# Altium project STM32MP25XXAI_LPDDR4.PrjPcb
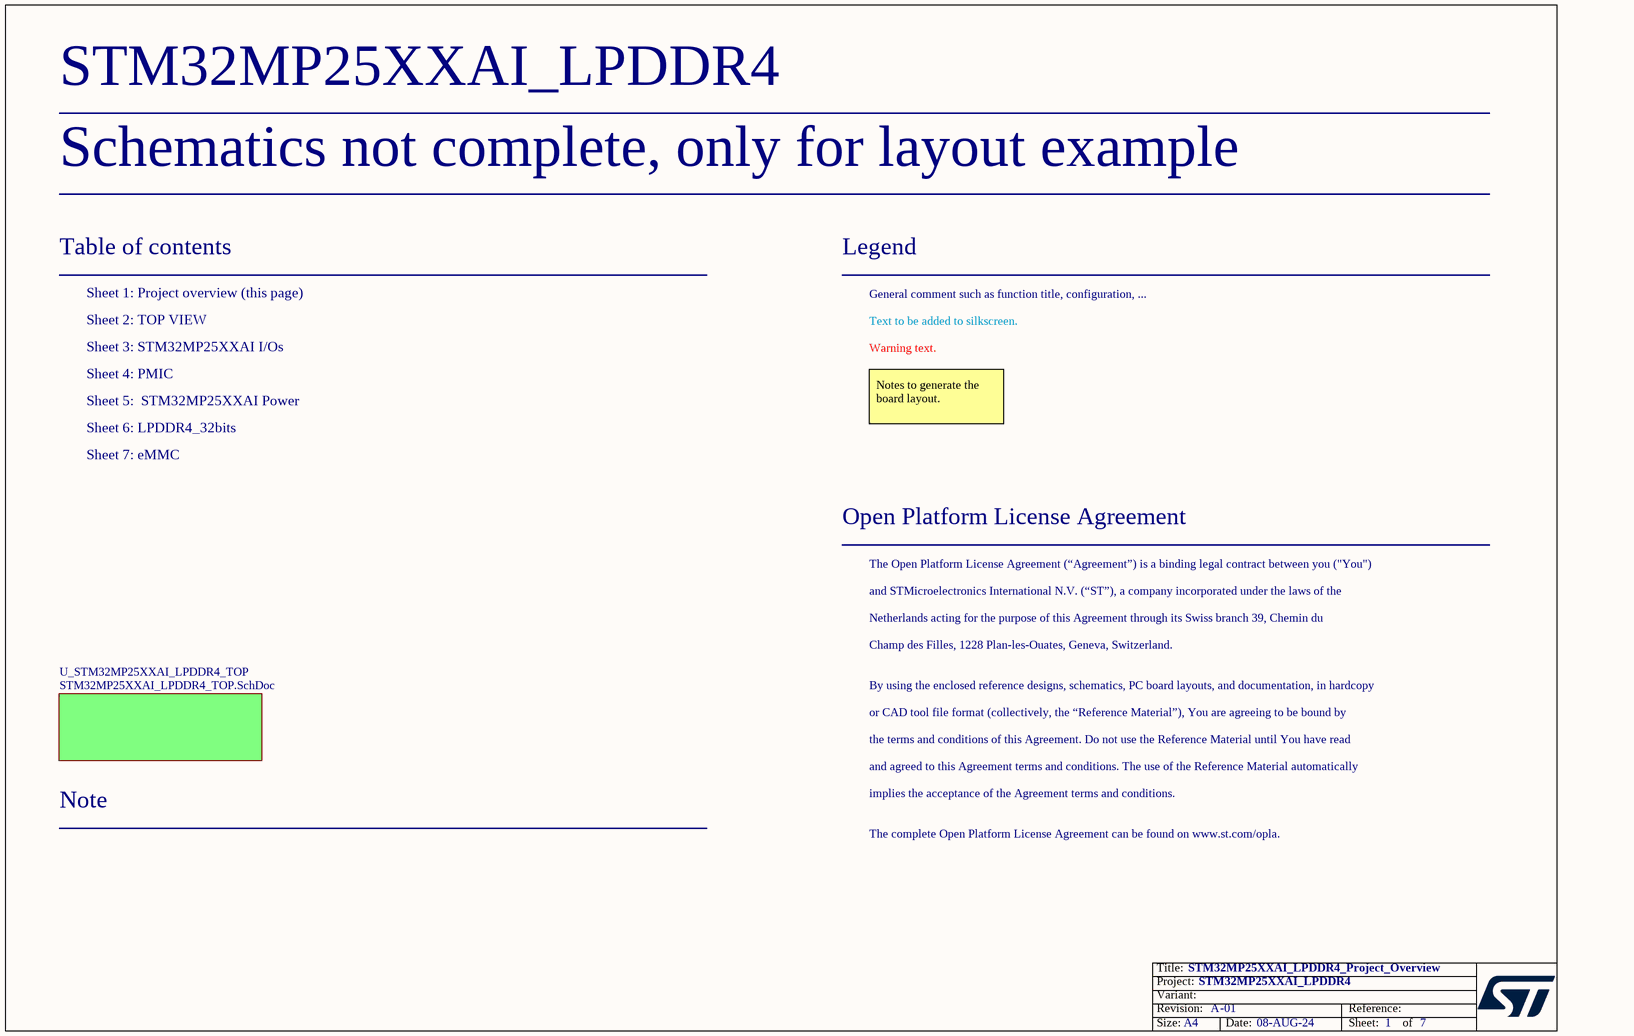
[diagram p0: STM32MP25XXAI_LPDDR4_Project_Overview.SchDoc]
Board_Assembly_Revision: 01; Board_Document_Date: 08-AUG-24; Board_Name: STM32MP25XXAI_LPDDR4; Board_PCB_Revision: A
7 sheets, 188 parts. Net scope: flat (ports and power ports of the same name join across sheets).
Board file: STM32MP25XXAI_LPDDR4.PcbDoc
Sheets:
  STM32MP25XXAI_LPDDR4_Project_Overview.SchDoc
    U_STM32MP25XXAI_LPDDR4_TOP = STM32MP25XXAI_LPDDR4_TOP.SchDoc
      U_STM32MP25XXAI I_Os = STM32MP25XXAI I_Os.SchDoc
      U_PMIC = PMIC.SchDoc
      U_STM32MP25XXAI Power = STM32MP25XXAI Power.SchDoc
      U_eMMC = eMMC.SchDoc
      U_2_LPDDR4_32bits = LPDDR4_32bits.SchDoc

## Sheet STM32MP25XXAI_LPDDR4_Project_Overview.SchDoc: STM32MP25XXAI_LPDDR4_Project_Overview
size A4; Date: Not used; ApprovedBy: Not used; CheckedBy: Not used; Author: Not used; CompanyName: STMicroelectronics; DrawnBy: Not used; Engineer: Not used; Organization: Not used; Address1: Not used; Address2: Not used; Address3: Not used; Address4: Not used; DocumentNumber: 1; Revision: Not used; SheetNumber: 1; SheetTotal: 7

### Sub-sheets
U_STM32MP25XXAI_LPDDR4_TOP = STM32MP25XXAI_LPDDR4_TOP.SchDoc: no entries

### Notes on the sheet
- Schematics not complete, only for layout example
- Table of contents
- Sheet 1: Project overview (this page)
- Legend
- General comment such as function title, configuration, ...
- Sheet 2: TOP VIEW
- Sheet 3: STM32MP25XXAI I/Os
- Sheet 4: PMIC
- Text to be added to silkscreen.
- Warning text.
- Sheet 5:  STM32MP25XXAI Power
- Sheet 6: LPDDR4_32bits
- Notes to generate the board layout.
- Sheet 7: eMMC
- Open Platform License Agreement
- The Open Platform License Agreement (“Agreement”) is a binding legal contract between you ("You")
- and STMicroelectronics International N.V. (“ST”), a company incorporated under the laws of the
- Netherlands acting for the purpose of this Agreement through its Swiss branch 39, Chemin du
- Champ des Filles, 1228 Plan-les-Ouates, Geneva, Switzerland.
- By using the enclosed reference designs, schematics, PC board layouts, and documentation, in hardcopy
- or CAD tool file format (collectively, the “Reference Material”), You are agreeing to be bound by
- the terms and conditions of this Agreement. Do not use the Reference Material until You have read
- and agreed to this Agreement terms and conditions. The use of the Reference Material automatically
- Note
- implies the acceptance of the Agreement terms and conditions.
- The complete Open Platform License Agreement can be found on www.st.com/opla.

## Sheet STM32MP25XXAI_LPDDR4_TOP.SchDoc: TOP
size A4; Date: Not used; ApprovedBy: Not used; CheckedBy: Not used; Author: Not used; CompanyName: STMicroelectronics; DrawnBy: Not used; Engineer: Not used; Organization: Not used; Address1: Not used; Address2: Not used; Address3: Not used; Address4: Not used; DocumentNumber: 2; Revision: Not used; SheetNumber: 2; SheetTotal: 7
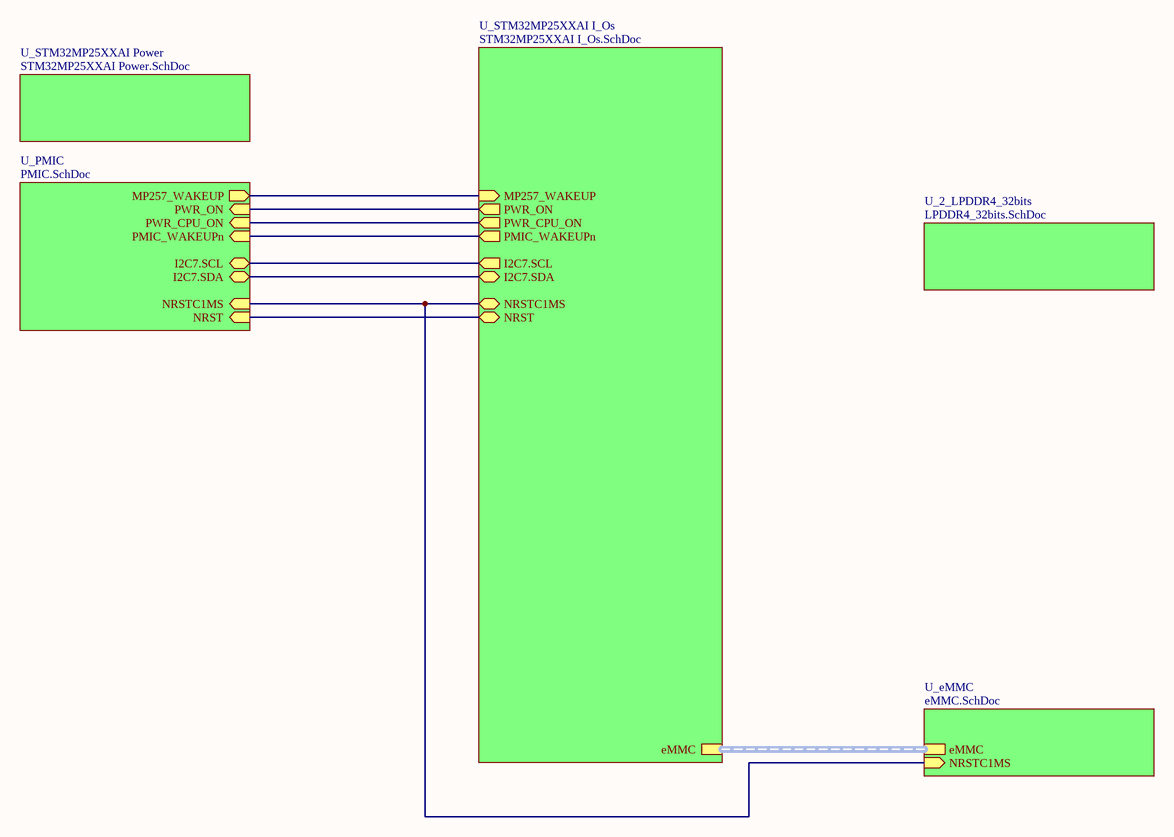
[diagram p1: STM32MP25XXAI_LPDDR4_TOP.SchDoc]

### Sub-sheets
U_2_LPDDR4_32bits = LPDDR4_32bits.SchDoc: no entries
U_eMMC = eMMC.SchDoc: eMMC (harness eMMC), NRSTC1MS (in)
U_PMIC = PMIC.SchDoc: PMIC_WAKEUPn (in), NRST (in), I2C7.SCL (bidir), PWR_ON (in), PWR_CPU_ON (in), NRSTC1MS (in), I2C7.SDA (bidir), MP257_WAKEUP (out)
U_STM32MP25XXAI I_Os = STM32MP25XXAI I_Os.SchDoc: NRST (bidir), PWR_ON (out), NRSTC1MS (bidir), I2C7.SDA (bidir), I2C7.SCL (out), PWR_CPU_ON (out), MP257_WAKEUP (in), PMIC_WAKEUPn (out), eMMC (harness eMMC)
U_STM32MP25XXAI Power = STM32MP25XXAI Power.SchDoc: no entries

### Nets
(unnamed): sheet U_STM32MP25XXAI I_Os/NRST, sheet U_PMIC/NRST
(unnamed): sheet U_STM32MP25XXAI I_Os/PWR_ON, sheet U_PMIC/PWR_ON  [a separate net that carries the same name]
(unnamed): sheet U_STM32MP25XXAI I_Os/NRSTC1MS, sheet U_PMIC/NRSTC1MS, sheet U_eMMC/NRSTC1MS  [a separate net that carries the same name]
(unnamed): sheet U_STM32MP25XXAI I_Os/I2C7.SDA, sheet U_PMIC/I2C7.SDA  [a separate net that carries the same name]
(unnamed): sheet U_STM32MP25XXAI I_Os/I2C7.SCL, sheet U_PMIC/I2C7.SCL  [a separate net that carries the same name]
(unnamed): sheet U_STM32MP25XXAI I_Os/PWR_CPU_ON, sheet U_PMIC/PWR_CPU_ON  [a separate net that carries the same name]
(unnamed): sheet U_STM32MP25XXAI I_Os/MP257_WAKEUP, sheet U_PMIC/MP257_WAKEUP  [a separate net that carries the same name]
(unnamed): sheet U_STM32MP25XXAI I_Os/PMIC_WAKEUPn, sheet U_PMIC/PMIC_WAKEUPn  [a separate net that carries the same name]

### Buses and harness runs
harness sheet U_eMMC/eMMC = sheet U_STM32MP25XXAI I_Os/eMMC

## Sheet STM32MP25XXAI I_Os.SchDoc: STM32MP25XXAI  I/Os
size A3; Date: Not used; ApprovedBy: Not used; CheckedBy: Not used; Author: Not used; CompanyName: STMicroelectronics; DrawnBy: Not used; Engineer: Not used; Organization: Not used; Address1: Not used; Address2: Not used; Address3: Not used; Address4: Not used; DocumentNumber: 3; Revision: Not used; SheetNumber: 3; SheetTotal: 7
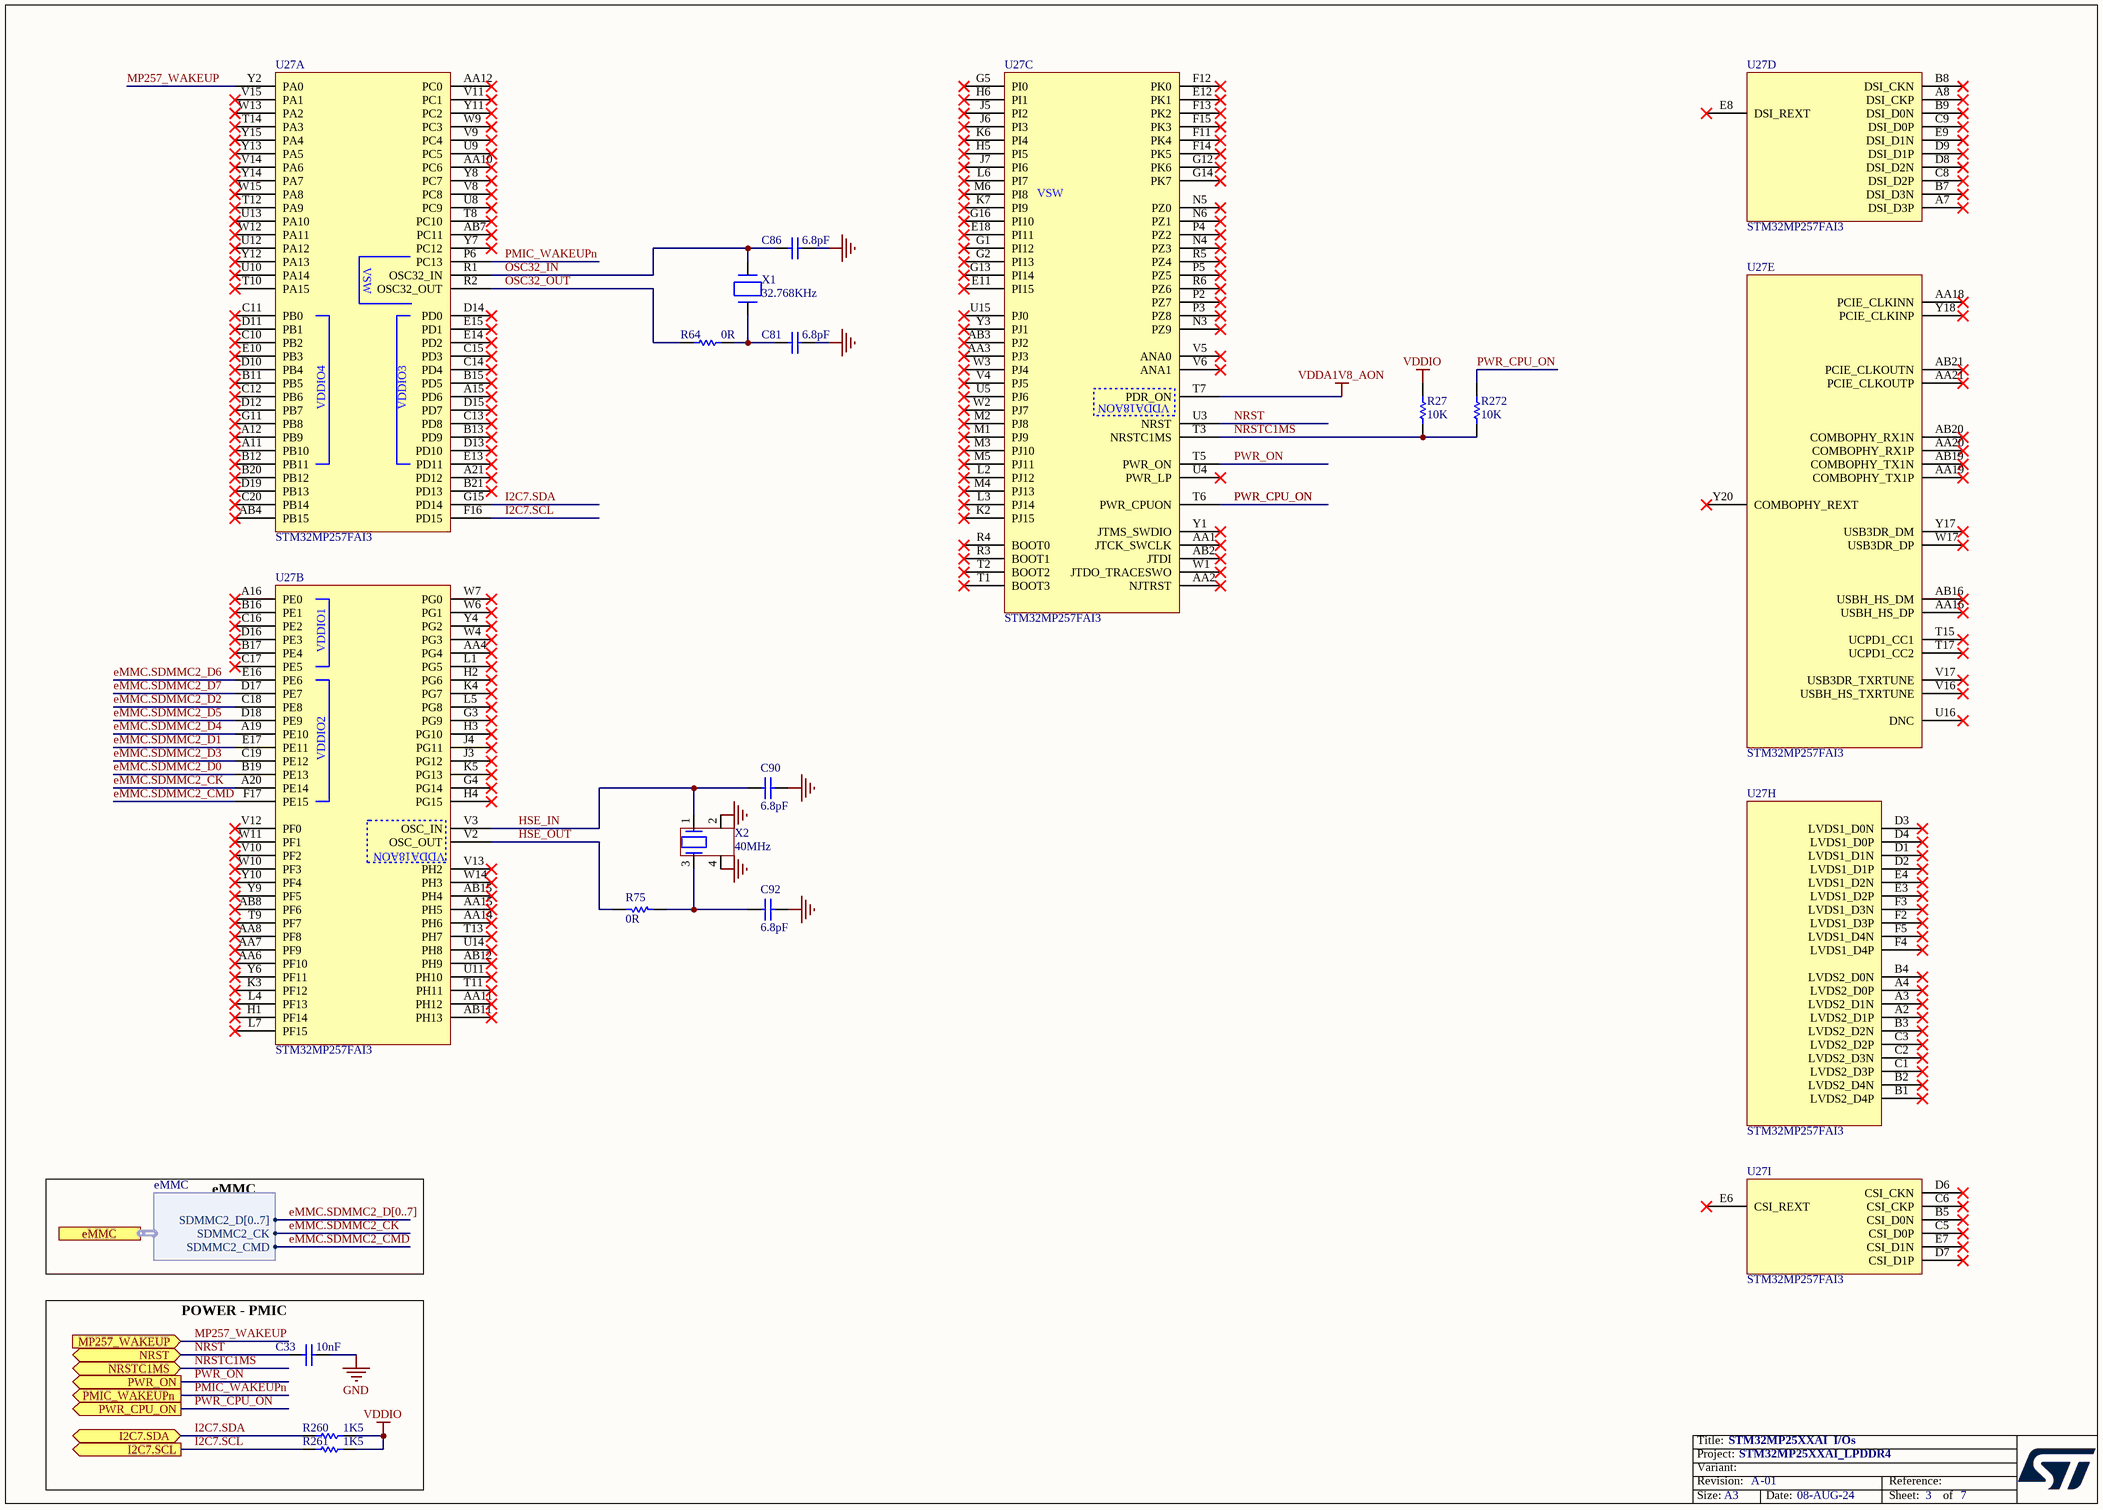
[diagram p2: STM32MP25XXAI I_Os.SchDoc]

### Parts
C33  value 10nF  [C0402]  (hidden comment: Capacitor)
C81  value 6.8pF  [C0402]  (hidden comment: Capacitor)
C86  value 6.8pF  [C0402]  (hidden comment: Capacitor)
C90  value 6.8pF  [C0402]  (hidden comment: Capacitor)
C92  value 6.8pF  [C0402]  (hidden comment: Capacitor)
R27  value 10K  [R0402]  (hidden comment: Resistor)
R64  value 0R  [R0402]
R75  value 0R  [R0402]
R260  value 1K5  [R0402]  (hidden comment: Resistor)
R261  value 1K5  [R0402]  (hidden comment: Resistor)
R272  value 10K  [R0402]  (hidden comment: Resistor)
U27  STM32MP257FAI3  [ICC_LFBGA436_18X18_P080_H1P70_STM32MP257_CODE-B0D1]  (parts A,B,C,D,E,H,I of 9)
X1  value 32.768KHz  [CRY_NX2012SA_2P]  (hidden comment: XTAL_2_PINS)
X2  value 40MHz  [CRY_NX1612SA_4P]  (hidden comment: XTAL_4_PINS)

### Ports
eMMC (harness eMMC), I2C7.SCL (out), I2C7.SDA (bidir), MP257_WAKEUP (in), NRST (bidir), NRSTC1MS (bidir), PMIC_WAKEUPn (out), PWR_CPU_ON (out), PWR_ON (out)

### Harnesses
eMMC: SDMMC2_CK, SDMMC2_CMD, SDMMC2_D[0..7]

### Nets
GND: C33.1 C81.2 C86.2 C90.1 C92.2 X2.2 X2.4
VDDA1V8_AON: U27.T7(PDR_ON)
VDDIO: R27.2 R260.2 R261.2
eMMC.SDMMC2_CK: U27.A20(PE14) ; port eMMC.SDMMC2_CK
eMMC.SDMMC2_CMD: U27.F17(PE15) ; port eMMC.SDMMC2_CMD
eMMC.SDMMC2_D0: U27.B19(PE13)
eMMC.SDMMC2_D1: U27.E17(PE11)
eMMC.SDMMC2_D2: U27.C18(PE8)
eMMC.SDMMC2_D3: U27.C19(PE12)
eMMC.SDMMC2_D4: U27.A19(PE10)
eMMC.SDMMC2_D5: U27.D18(PE9)
eMMC.SDMMC2_D6: U27.E16(PE6)
eMMC.SDMMC2_D7: U27.D17(PE7)
HSE_IN: C90.2 U27.V3(OSC_IN) X2.1
HSE_OUT: R75.2 U27.V2(OSC_OUT)
I2C7.SCL: R261.1 U27.F16(PD15) ; port I2C7.SCL
I2C7.SDA: R260.1 U27.G15(PD14) ; port I2C7.SDA
MP257_WAKEUP: U27.Y2(PA0) ; port MP257_WAKEUP
NRST: C33.2 U27.U3(NRST) ; port NRST
NRSTC1MS: R27.1 R272.1 U27.T3(NRSTC1MS) ; port NRSTC1MS
OSC32_IN: C86.1 U27.R1(OSC32_IN) X1.2(X2)
OSC32_OUT: R64.1 U27.R2(OSC32_OUT)
PMIC_WAKEUPn: U27.P6(PC13) ; port PMIC_WAKEUPn
PWR_CPU_ON: R272.2 U27.T6(PWR_CPUON) ; port PWR_CPU_ON
PWR_ON: U27.T5(PWR_ON) ; port PWR_ON
NetC81_1: C81.1 R64.2 X1.1(X1)
NetC92_1: C92.1 R75.1 X2.3

Not connected (* = marked no-connect by the designer): U27 A2(LVDS2_D1P)* A3(LVDS2_D1N)* A4(LVDS2_D0P)* A7(DSI_D3P)* A8(DSI_CKP)* A11(PB10)* A12(PB9)* A15(PD6)* A16(PE0)* A21(PD12)* AA1(JTCK_SWCLK)* AA2(NJTRST)* AA3(PJ3)* AA4(PG4)* AA6(PF10)* AA7(PF9)* AA8(PF8)* AA10(PC6)* AA11(PH12)* AA12(PC0)* AA14(PH6)* AA15(PH5)* AA16(USBH_HS_DP)* AA18(PCIE_CLKINN)* AA19(COMBOPHY_TX1P)* AA20(COMBOPHY_RX1P)* AA21(PCIE_CLKOUTP)* AB2(JTDI)* AB3(PJ2)* AB4(PB15)* AB7(PC11)* AB8(PF6)* AB11(PH13)* AB12(PH9)* AB15(PH4)* AB16(USBH_HS_DM)* AB19(COMBOPHY_TX1N)* AB20(COMBOPHY_RX1N)* AB21(PCIE_CLKOUTN)* B1(LVDS2_D4P)* B2(LVDS2_D4N)* B3(LVDS2_D2N)* B4(LVDS2_D0N)* B5(CSI_D0N)* B7(DSI_D3N)* B8(DSI_CKN)* B9(DSI_D0N)* B11(PB5)* B12(PB11)* B13(PD9)* B15(PD5)* B16(PE1)* B17(PE4)* B20(PB12)* B21(PD13)* C1(LVDS2_D3P)* C2(LVDS2_D3N)* C3(LVDS2_D2P)* C5(CSI_D0P)* C6(CSI_CKP)* C8(DSI_D2P)* C9(DSI_D0P)* C10(PB2)* C11(PB0)* C12(PB6)* C13(PD8)* C14(PD4)* C15(PD3)* C16(PE2)* C17(PE5)* C20(PB14)* D1(LVDS1_D1N)* D2(LVDS1_D1P)* D3(LVDS1_D0N)* D4(LVDS1_D0P)* D6(CSI_CKN)* D7(CSI_D1P)* D8(DSI_D2N)* D9(DSI_D1P)* D10(PB4)* D11(PB1)* D12(PB7)* D13(PD10)* D14(PD0)* D15(PD7)* D16(PE3)* D19(PB13)* E3(LVDS1_D2P)* E4(LVDS1_D2N)* E6(CSI_REXT)* E7(CSI_D1N)* E8(DSI_REXT)* E9(DSI_D1N)* E10(PB3)* E11(PI15)* E12(PK1)* E13(PD11)* E14(PD2)* E15(PD1)* E18(PI11)* F2(LVDS1_D3P)* F3(LVDS1_D3N)* F4(LVDS1_D4P)* F5(LVDS1_D4N)* F11(PK4)* F12(PK0)* F13(PK2)* F14(PK5)* F15(PK3)* G1(PI12)* G2(PI13)* G3(PG9)* G4(PG14)* G5(PI0)* G11(PB8)* G12(PK6)* G13(PI14)* G14(PK7)* G16(PI10)* H1(PF14)* H2(PG6)* H3(PG10)* H4(PG15)* H5(PI5)* H6(PI1)* J3(PG12)* J4(PG11)* J5(PI2)* J6(PI3)* J7(PI6)* K2(PJ15)* K3(PF12)* K4(PG7)* K5(PG13)* K6(PI4)* K7(PI9)* L1(PG5)* L2(PJ12)* L3(PJ14)* L4(PF13)* L5(PG8)* L6(PI7)* L7(PF15)* M1(PJ9)* M2(PJ8)* M3(PJ10)* M4(PJ13)* M5(PJ11)* M6(PI8)* N3(PZ9)* N4(PZ3)* N5(PZ0)* N6(PZ1)* P2(PZ7)* P3(PZ8)* P4(PZ2)* P5(PZ5)* R3(BOOT1)* R4(BOOT0)* R5(PZ4)* R6(PZ6)* T1(BOOT3)* T2(BOOT2)* T8(PC10)* T9(PF7)* T10(PA15)* T11(PH11)* T12(PA9)* T13(PH7)* T14(PA3)* T15(UCPD1_CC1)* T17(UCPD1_CC2)* U4(PWR_LP)* U5(PJ6)* U8(PC9)* U9(PC5)* U10(PA14)* U11(PH10)* U12(PA12)* U13(PA10)* U14(PH8)* U15(PJ0)* U16(DNC)* V4(PJ5)* V5(ANA0)* V6(ANA1)* V8(PC8)* V9(PC4)* V10(PF2)* V11(PC1)* V12(PF0)* V13(PH2)* V14(PA6)* V15(PA1)* V16(USBH_HS_TXRTUNE)* V17(USB3DR_TXRTUNE)* W1(JTDO_TRACESWO)* W2(PJ7)* W3(PJ4)* W4(PG3)* W6(PG1)* W7(PG0)* W9(PC3)* W10(PF3)* W11(PF1)* W12(PA11)* W13(PA2)* W14(PH3)* W15(PA8)* W17(USB3DR_DP)* Y1(JTMS_SWDIO)* Y3(PJ1)* Y4(PG2)* Y6(PF11)* Y7(PC12)* Y8(PC7)* Y9(PF5)* Y10(PF4)* Y11(PC2)* Y12(PA13)* Y13(PA5)* Y14(PA7)* Y15(PA4)* Y17(USB3DR_DM)* Y18(PCIE_CLKINP)* Y20(COMBOPHY_REXT)*

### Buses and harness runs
bus eMMC.SDMMC2_D[0..7]

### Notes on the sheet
- eMMC
- POWER - PMIC

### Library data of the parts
C33 = MCD-00011: Capacitor, MLCC, 10nF, 16V, X7R, 10%, 0402, T=0.5mm; Manufacturer_Part_Number: CC0402KRX7R7BB103; Manufacturer: YAGEO; Provided_By: SUBCO; Initial_Board_Reference: MB1274
C81 C86 = MCD-00674: Capacitor, MLCC, 6.8pF, 50V, NPO, +-0.25pF, 0402, T=0.5mm; Manufacturer_Part_Number: CC0402CRNPO9BN6R8; Manufacturer: YAGEO; Part_Preference: Recommended; Provided_By: SUBCO; Initial_Board_Reference: MB1319; Path: ws/MCD_ApplicationBoards/Lists/MCDPARTSdatabase; Item Type: Item; Component_Country_Of_Origin: China; ID: 3068; ShowFields: YES
C90 C92 = MCD-00674: Capacitor, MLCC, 6.8pF, 50V, NPO, +-0.25pF, 0402, T=0.5mm; Manufacturer_Part_Number: CC0402CRNPO9BN6R8; Manufacturer: YAGEO; Part_Preference: Recommended; Provided_By: SUBCO; Initial_Board_Reference: MB1319; Component_Country_Of_Origin: China; ID: 3068; ShowFields: YES
R27 R272 = MCD-00053: Resistor,10K,0402,1%,1/16W; BMS_Part_Number: 9131590; Part_Preference: Recommended; Manufacturer: YAGEO; Manufacturer_Part_Number: RC0402FR-0710KL; Component_Country_Of_Origin: China; ID: 2539; ShowFields: YES
R64 R75 = MCD-00052: Resistor,0R,0402,5%,1/16W; Manufacturer_Part_Number: RC0402JR-070RL; Manufacturer: YAGEO; Part_Preference: Recommended; Provided_By: SUBCO; Initial_Board_Reference: mb1274; Order_Code_RS: 618-5804; Component_Country_Of_Origin: China; ID: 2540; ShowFields: YES
R260 R261 = MCD-00068: Resistor,1K5,0402,1%,1/16W; Part_Preference: Recommended; Manufacturer: YAGEO; Manufacturer_Part_Number: RC0402FR-071K5L; Component_Country_Of_Origin: China; ID: 2524; ShowFields: YES
U27 = MCD-02000: MPU, ARM Cortex-A35 + M33 32-bit MPU, 808KB RAM, With Crypto; Part_Type: IC; Part_Preference: Recommended; Manufacturer: STMICROELECTRONICS; Manufacturer_HQ_COO: EU; Component_Country_Of_Origin: Unknown; ShowFields: YES; ID: 4100
X1 = MCD-01479: Crystal, 32.768kHz, 6pF, +/-20ppm, 80K, 2.05x1.2mm; BMS_Part_Number: 9157049; Part_Type: Crystal_Osc; Part_Preference: Recommended; Manufacturer: NDK; Manufacturer_Part_Number: NX2012SA-32.768KHZ-EXS00A-MU00527; Component_Country_Of_Origin: Unknown; ShowFields: YES; ID: 3579
X2 = MCD-02344: Crystal, 40MHz, 6pF, +/-20ppm, 80R, 1.6x1.2mm; Part_Type: Crystal_Osc; Part_Preference: Recommended; Manufacturer: NDK; Manufacturer_Part_Number: NX1612SA-40MHZ-EXS00A-CS13836; Component_Country_Of_Origin: Unknown; ShowFields: YES; ID: 4450

## Sheet PMIC.SchDoc: PMIC
size A3; Date: Not used; ApprovedBy: Not used; CheckedBy: Not used; Author: Not used; CompanyName: STMicroelectronics; DrawnBy: Not used; Engineer: Not used; Organization: Not used; Address1: Not used; Address2: Not used; Address3: Not used; Address4: Not used; DocumentNumber: 4; Revision: Not used; SheetNumber: 4; SheetTotal: 7
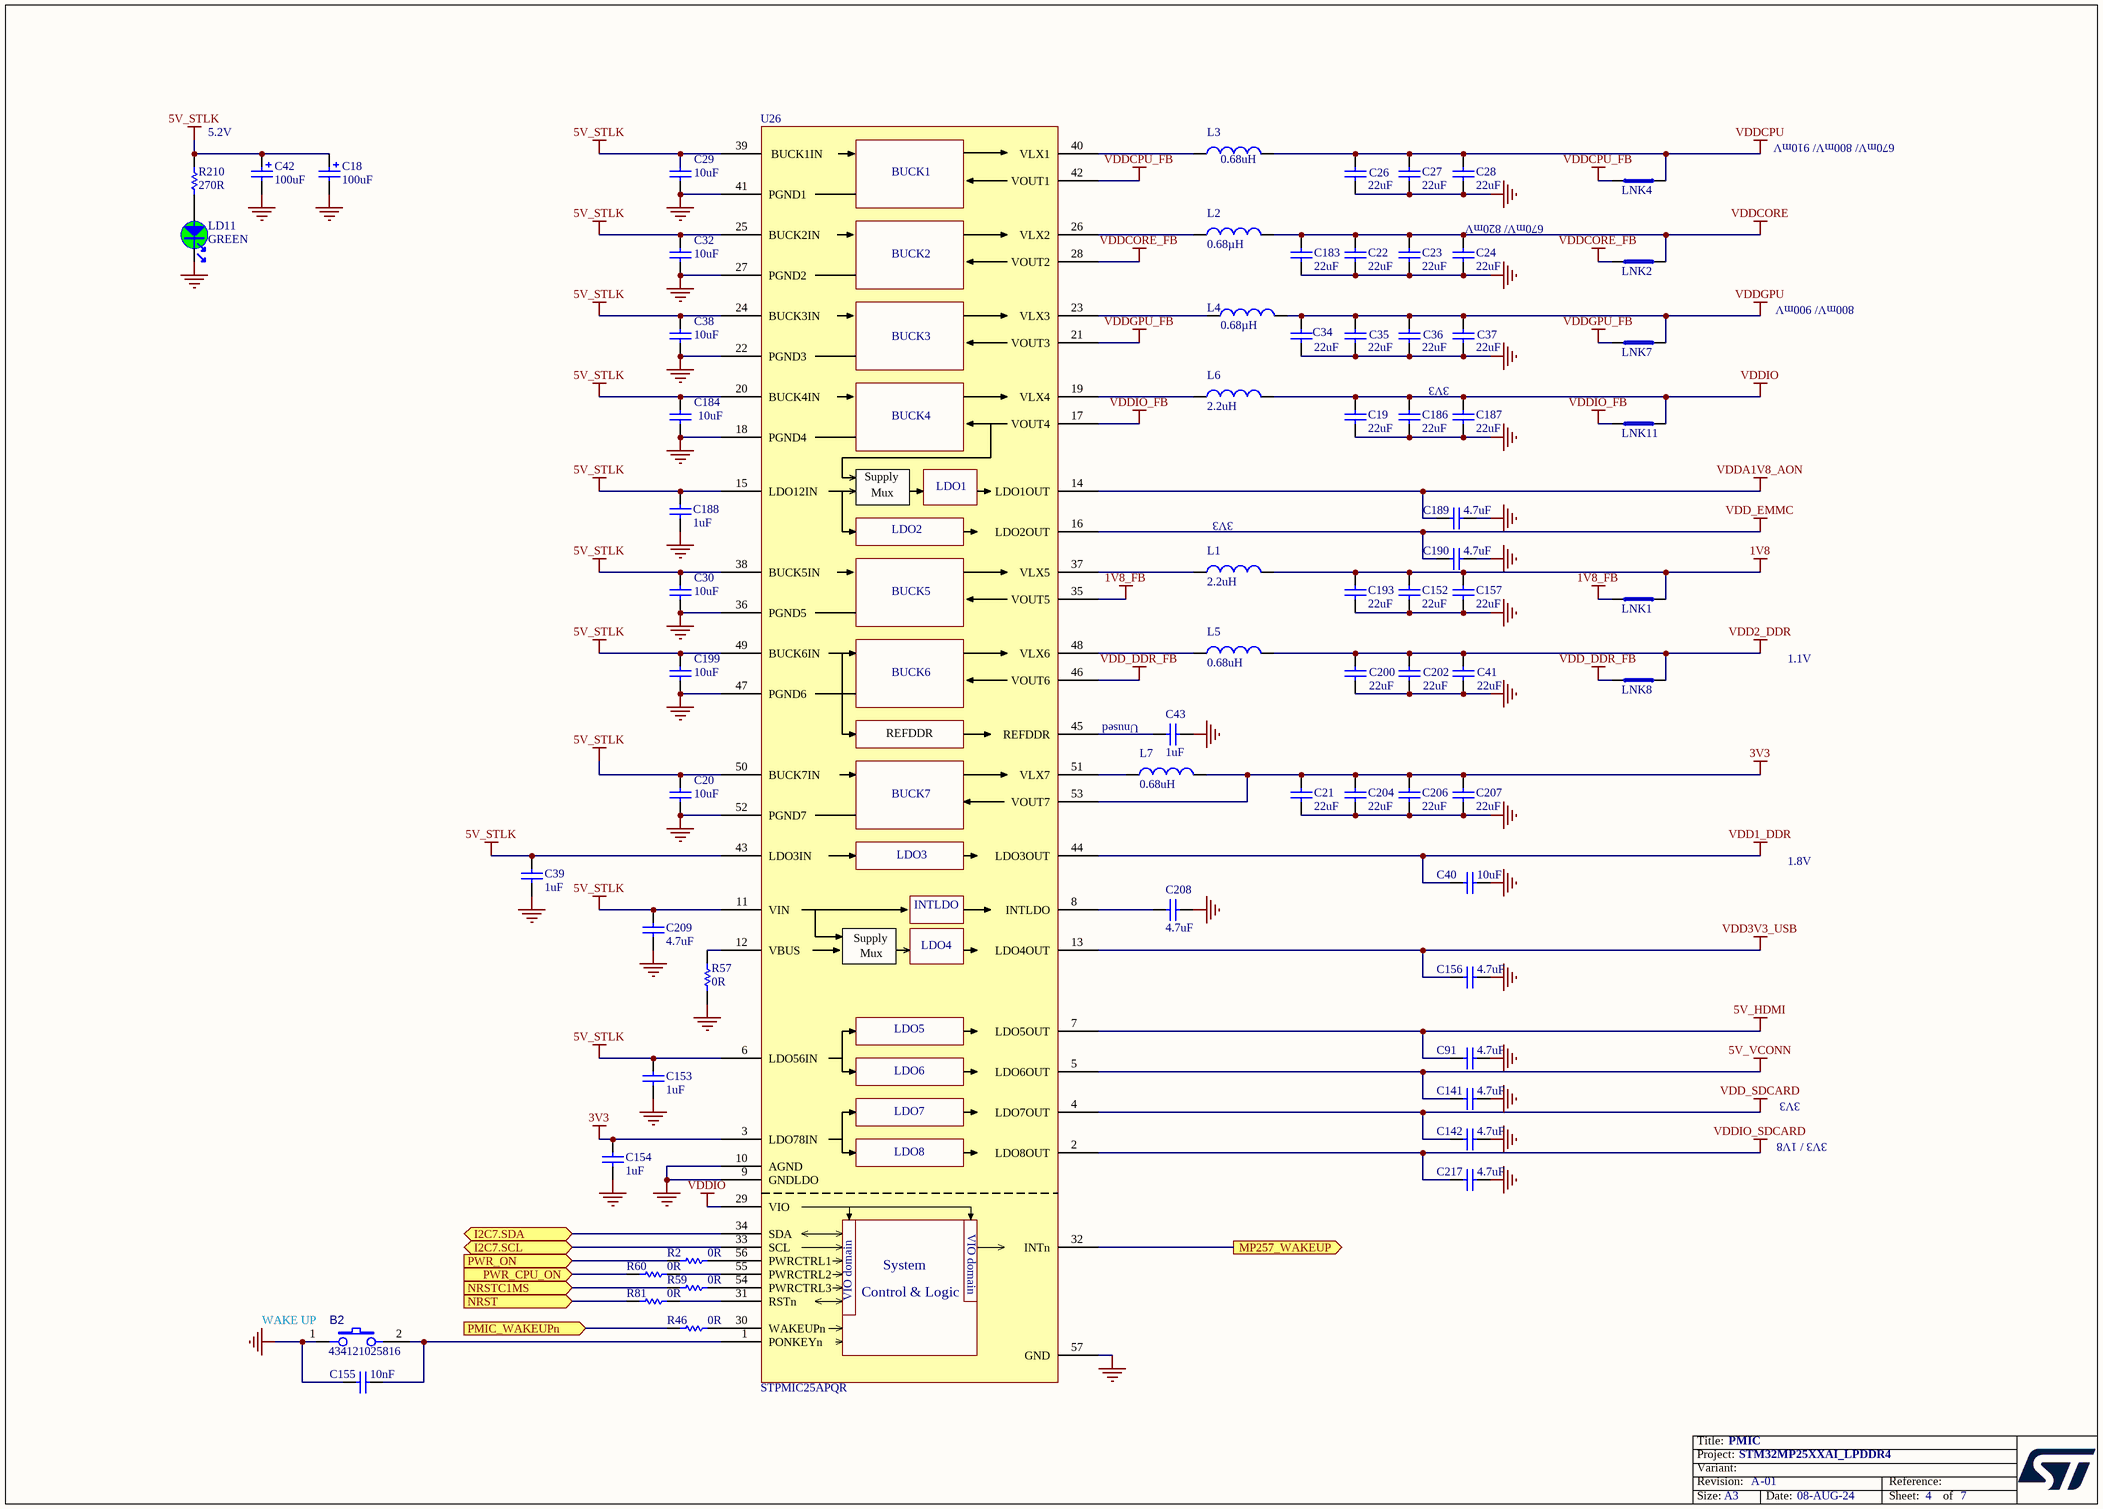
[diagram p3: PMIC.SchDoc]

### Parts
B2  value 434121025816  [SWI_WE_434121025816]  (hidden comment: SW_PUSH_SMD_2P)
C18  value 100uF  [CPOL_TCJ-B_1210_H210]  (hidden comment: Cap_POL_TANA)
C19  value 22uF  [C0805]  (hidden comment: Capacitor)
C20  value 10uF  [C0603]  (hidden comment: Capacitor)
C21  value 22uF  [C0805]  (hidden comment: Capacitor)
C22  value 22uF  [C0603]  (hidden comment: Capacitor)
C23  value 22uF  [C0603]  (hidden comment: Capacitor)
C24  value 22uF  [C0603]  (hidden comment: Capacitor)
C26  value 22uF  [C0603]  (hidden comment: Capacitor)
C27  value 22uF  [C0603]  (hidden comment: Capacitor)
C28  value 22uF  [C0603]  (hidden comment: Capacitor)
C29  value 10uF  [C0603]  (hidden comment: Capacitor)
C30  value 10uF  [C0603]  (hidden comment: Capacitor)
C32  value 10uF  [C0603]  (hidden comment: Capacitor)
C34  value 22uF  [C0603]  (hidden comment: Capacitor)
C35  value 22uF  [C0603]  (hidden comment: Capacitor)
C36  value 22uF  [C0603]  (hidden comment: Capacitor)
C37  value 22uF  [C0603]  (hidden comment: Capacitor)
C38  value 10uF  [C0603]  (hidden comment: Capacitor)
C39  value 1uF  [C0402]  (hidden comment: Capacitor)
C40  value 10uF  [C0402]  (hidden comment: Capacitor)
C41  value 22uF  [C0603]  (hidden comment: Capacitor)
C42  value 100uF  [CPOL_TCJ-B_1210_H210]  (hidden comment: Cap_POL_TANA)
C43  value 1uF  [C0402]  (hidden comment: Capacitor)
C91  value 4.7uF  [C0402]  (hidden comment: Capacitor)
C141  value 4.7uF  [C0402]  (hidden comment: Capacitor)
C142  value 4.7uF  [C0402]  (hidden comment: Capacitor)
C152  value 22uF  [C0805]  (hidden comment: Capacitor)
C153  value 1uF  [C0402]  (hidden comment: Capacitor)
C154  value 1uF  [C0402]  (hidden comment: Capacitor)
C155  value 10nF  [C0402]  (hidden comment: Capacitor)
C156  value 4.7uF  [C0402]  (hidden comment: Capacitor)
C157  value 22uF  [C0805]  (hidden comment: Capacitor)
C183  value 22uF  [C0603]  (hidden comment: Capacitor)
C184  value 10uF  [C0603]  (hidden comment: Capacitor)
C186  value 22uF  [C0805]  (hidden comment: Capacitor)
C187  value 22uF  [C0805]  (hidden comment: Capacitor)
C188  value 1uF  [C0402]  (hidden comment: Capacitor)
C189  value 4.7uF  [C0402]  (hidden comment: Capacitor)
C190  value 4.7uF  [C0402]  (hidden comment: Capacitor)
C193  value 22uF  [C0805]  (hidden comment: Capacitor)
C199  value 10uF  [C0603]  (hidden comment: Capacitor)
C200  value 22uF  [C0603]  (hidden comment: Capacitor)
C202  value 22uF  [C0603]  (hidden comment: Capacitor)
C204  value 22uF  [C0805]  (hidden comment: Capacitor)
C206  value 22uF  [C0805]  (hidden comment: Capacitor)
C207  value 22uF  [C0805]  (hidden comment: Capacitor)
C208  value 4.7uF  [C0402]  (hidden comment: Capacitor)
C209  value 4.7uF  [C0402]  (hidden comment: Capacitor)
C217  value 4.7uF  [C0402]  (hidden comment: Capacitor)
L1  value 2.2uH  [IND_2016_MURATA_LQM2MPN2R2NG0]  (hidden comment: Inductor)
L2  value 0.68µH  [IND_2520_TOKO_DFE252012P]  (hidden comment: Inductor)
L3  value 0.68uH  [IND_2016_MURATA_LQM2MPN2R2NG0]  (hidden comment: Inductor)
L4  value 0.68µH  [IND_2520_TOKO_DFE252012P]  (hidden comment: Inductor)
L5  value 0.68uH  [IND_2016_MURATA_LQM2MPN2R2NG0]  (hidden comment: Inductor)
L6  value 2.2uH  [IND_2016_MURATA_LQM2MPN2R2NG0]  (hidden comment: Inductor)
L7  value 0.68uH  [IND_2016_MURATA_LQM2MPN2R2NG0]  (hidden comment: Inductor)
LD11  value GREEN  [LED_0603_OSRAM_LG-Q396-PS-35_GREEN_1A2K_H0P4]  (hidden comment: LED_green)
LNK1  link_200  [LINK200]  (value not drawn)  (no BOM)
LNK2  link_200  [LINK200]  (value not drawn)  (no BOM)
LNK4  link_200  [LINK200]  (value not drawn)  (no BOM)
LNK7  link_200  [LINK200]  (value not drawn)  (no BOM)
LNK8  link_200  [LINK200]  (value not drawn)  (no BOM)
LNK11  link_200  [LINK200]  (value not drawn)  (no BOM)
R2  value 0R  [R0402]
R46  value 0R  [R0402]
R57  value 0R  [R0402]
R59  value 0R  [R0402]
R60  value 0R  [R0402]
R81  value 0R  [R0402]
R210  value 270R  [R0402]  (hidden comment: Resistor)
U26  STPMIC25APQR  [ICC_QFN56-EPAD_6P5X6P5_P040]

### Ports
I2C7.SCL (bidir), I2C7.SDA (bidir), MP257_WAKEUP (out), NRST (in), NRSTC1MS (in), PMIC_WAKEUPn (in), PWR_CPU_ON (in), PWR_ON (in)

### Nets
1V8: C152.2 C157.2 C193.2 L1.2 LNK1.2
1V8_FB: LNK1.1 U26.35(VOUT5)
3V3: C21.2 C154.2 C204.2 C206.2 C207.2 L7.2 U26.3(LDO78IN) U26.53(VOUT7)
5V_HDMI: C91.1 U26.7(LDO5OUT)
5V_STLK: C18.1 C20.2 C29.2 C30.2 C32.2 C38.2 C39.2 C42.1 C153.2 C184.2 C188.2 C199.2 C209.2 R210.1 U26.6(LDO56IN) U26.11(VIN) U26.15(LDO12IN) U26.20(BUCK4IN) U26.24(BUCK3IN) U26.25(BUCK2IN) U26.38(BUCK5IN) U26.39(BUCK1IN) U26.43(LDO3IN) U26.49(BUCK6IN) U26.50(BUCK7IN)
5V_VCONN: C141.1 U26.5(LDO6OUT)
GND: B2.1 C18.2 C19.1 C20.1 C21.1 C22.1 C23.1 C24.1 C26.1 C27.1 C28.1 C29.1 C30.1 C32.1 C34.1 C35.1 C36.1 C37.1 C38.1 C39.1 C40.1 C41.1 C42.2 C43.1 C91.2 C141.2 C142.2 C152.1 C153.1 C154.1 C155.1 C156.1 C157.1 C183.1 C184.1 C186.1 C187.1 C188.1 C189.1 C190.2 C193.1 C199.1 C200.1 C202.1 C204.1 C206.1 C207.1 C208.2 C209.1 C217.2 LD11.2 R57.1 U26.9(GNDLDO) U26.10(AGND) U26.18(PGND4) U26.22(PGND3) U26.27(PGND2) U26.36(PGND5) U26.41(PGND1) U26.47(PGND6) U26.52(PGND7) U26.57(GND)
VDD1_DDR: C40.2 U26.44(LDO3OUT)
VDD2_DDR: C41.2 C200.2 C202.2 L5.2 LNK8.2
VDD3V3_USB: C156.2 U26.13(LDO4OUT)
VDD_DDR_FB: LNK8.1 U26.46(VOUT6)
VDD_EMMC: C190.1 U26.16(LDO2OUT)
VDD_SDCARD: C142.1 U26.4(LDO7OUT)
VDDA1V8_AON: C189.2 U26.14(LDO1OUT)
VDDCORE: C22.2 C23.2 C24.2 C183.2 L2.2 LNK2.2
VDDCORE_FB: LNK2.1 U26.28(VOUT2)
VDDCPU: C26.2 C27.2 C28.2 L3.2 LNK4.1
VDDCPU_FB: LNK4.2 U26.42(VOUT1)
VDDGPU: C34.2 C35.2 C36.2 C37.2 L4.2 LNK7.2
VDDGPU_FB: LNK7.1 U26.21(VOUT3)
VDDIO: C19.2 C186.2 C187.2 L6.2 LNK11.2 U26.29(VIO)
VDDIO_FB: LNK11.1 U26.17(VOUT4)
VDDIO_SDCARD: C217.1 U26.2(LDO8OUT)
I2C7.SCL: U26.33(SCL) ; port I2C7.SCL
I2C7.SDA: U26.34(SDA) ; port I2C7.SDA
MP257_WAKEUP: U26.32(INTn) ; port MP257_WAKEUP
NRST: R81.1 ; port NRST
NRSTC1MS: R59.1 ; port NRSTC1MS
PMIC_WAKEUPn: R46.1 ; port PMIC_WAKEUPn
PWR_CPU_ON: R60.1 ; port PWR_CPU_ON
PWR_ON: R2.1 ; port PWR_ON
NetB2_2: B2.2 C155.2 U26.1(PONKEYn)
NetC43_2: C43.2 U26.45(REFDDR)
NetC208_1: C208.1 U26.8(INTLDO)
NetL1_1: L1.1 U26.37(VLX5)
NetL2_1: L2.1 U26.26(VLX2)
NetL3_1: L3.1 U26.40(VLX1)
NetL4_1: L4.1 U26.23(VLX3)
NetL5_1: L5.1 U26.48(VLX6)
NetL6_1: L6.1 U26.19(VLX4)
NetL7_1: L7.1 U26.51(VLX7)
NetLD11_1: LD11.1 R210.2
NetR2_2: R2.2 U26.56(PWRCTRL1)
NetR46_2: R46.2 U26.30(WAKEUPn)
NetR57_2: R57.2 U26.12(VBUS)
NetR59_2: R59.2 U26.54(PWRCTRL3)
NetR60_2: R60.2 U26.55(PWRCTRL2)
NetR81_2: R81.2 U26.31(RSTn)

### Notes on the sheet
- 5.2V
- 670mV/ 800mV/ 910mV
- (near C24) 670mV/ 820mV
- 800mV/ 900mV
- 3V3
- (near L1) 3V3
- Unused
- 1.1V
- 1.8V
- 3V3 / 1V8
- (near B2) WAKE UP

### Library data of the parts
B2 = MCD-03492: Switch tactile, SPST-NO, 50mA, 12V, 6x3.8mm; Part_Type: Misc; Part_Preference: Recommended; Manufacturer: WURTH ELEKTRONIC; Component_Country_Of_Origin: China°; ShowFields: YES; ID: 5608
C18 C42 = MCD-01796: Capacitor, Tantalum, 100uF, 6V3, 40mR, +/-20%,  Type_B (3528 metric), T=1.9mm; Part_Preference: Recommended; Manufacturer: AVX; Manufacturer_Part_Number: TCJB107M006R0040; Component_Country_Of_Origin: Lanskroun; ShowFields: YES; ID: 3896
C19 C21 C152 C157 C186 C187 C193 C204 C206 C207 = MCD-03139: Capacitor, MLCC, 22uF, 10V, X5R, +/-20%, 0805, T=1,25mm; Part_Preference: Recommended; Manufacturer: MURATA; Manufacturer_Part_Number: GRM21BR61A226ME51L; ShowFields: YES; ID: 5255; Component_Country_Of_Origin: China, Japan
C20 C29 C30 C32 C38 C184 C199 = MCD-00099: Capacitor, MLCC, 10uF, 10V, X5R, +/-10%, 0603, T=0,8mm; Manufacturer_Part_Number: GRM188R61A106KE69D; Manufacturer: MURATA; Part_Preference: Recommended; Order_Code_RS: 170-6168; Component_Country_Of_Origin: Japan; ID: 2770; ShowFields: YES
C22-C24 C26 C34-C37 C41 C200 C202 = MCD-00100: Capacitor, MLCC, 22uF, 6V3, X5R, +/-20%, 0603, T=0,8mm; Manufacturer_Part_Number: GRM188R60J226MEA0J; Manufacturer: MURATA; Part_Preference: Recommended; Component_Country_Of_Origin: Japan; ID: 2766; ShowFields: YES
C27 C28 C183 = MCD-00100: Capacitor, MLCC, 22uF, 6V3, X5R, +/-20%, 0603, T=0,8mm; Part_Preference: Recommended; Manufacturer: MURATA; Manufacturer_Part_Number: GRM188R60J226MEA0J; Component_Country_Of_Origin: Japan; ID: 2766; ShowFields: YES
C39 C43 C153 C154 C188 = MCD-00095: Capacitor, MLCC, 1uF, 25V, X5R, +/-10%, 0402, T=0.5mm; Part_Preference: Recommended; Manufacturer: MURATA; Manufacturer_Part_Number: GRM155R61E105KA12; Order_Code_RS: 846-7287; Component_Country_Of_Origin: Japan; ShowFields: YES; ID: 2772
C40 = MCD-03140: Capacitor, MLCC, 10uF, 6.3V, X5R, +/-20%, 0402, T=0.5mm; Part_Preference: Recommended; Manufacturer: MURATA; Manufacturer_Part_Number: GRM155R60J106ME05D; ShowFields: YES; ID: 5256; Component_Country_Of_Origin: China, Japan
C91 C141 C142 C156 C189 C190 C208 C209 C217 = MCD-01356: Capacitor, MLCC, 4.7uF, 6V3, X5R, +/-20%, 0402, T=0.5mm; Manufacturer_Part_Number: GRM155R60J475ME47; Manufacturer: MURATA; Part_Preference: Recommended; Order_Code_RS: 814-5230; Component_Country_Of_Origin: Japan; ShowFields: YES; ID: 3456
C155 = MCD-02198: Capacitor, MLCC, 10nF, 50V, X7R, +/-10%, 0402, T=0.5mm; Manufacturer_Part_Number: CC0402KRX7R9BB103; Manufacturer: YAGEO; Part_Preference: Recommended; Order_Code_RS: 6169644; Component_Country_Of_Origin: China; ShowFields: YES; ID: 4298
L1 L6 = MCD-03143: Inductor, 2.2uH, +/-20%, Itemp= 1700mA, Isat= 2400mA, 0R140, 0806, T=1mm; Part_Preference: Recommended; Manufacturer: MURATA; Manufacturer_Part_Number: DFE201610E-2R2M=P2; ShowFields: YES; ID: 5259; Component_Country_Of_Origin: Vietnam
L2 L4 = MCD-03142: Inductor, 0.68uH, +/-20%, Itemp= 3900mA, Isat= 5400mA, 0R031, 1008, T=1.2mm; Part_Preference: Recommended; Manufacturer: MURATA; Manufacturer_Part_Number: DFE252012F-R68M=P2; ShowFields: YES; ID: 5258; Component_Country_Of_Origin: Vietnam
L3 L5 L7 = MCD-03141: Inductor, 0.68uH, +/-20%, Itemp= 3100mA, Isat= 4300mA, 0R043, 0806, T=1mm; Part_Preference: Recommended; Manufacturer: MURATA; Manufacturer_Part_Number: DFE201610E-R68M=P2; ShowFields: YES; ID: 5257; Component_Country_Of_Origin: Vietnam
LD11 = MCD-00588: LED Green, 0603 SMD, Forward Voltage Typ=2V, Max=2.5V; Part_Type: Display; Manufacturer_Part_Number: LG Q396-PS-35; Manufacturer: OSRAM OPTO SEMICONDUCTORS; Alternate_Manufacturer_Part_Number: VLMTG1300-GS08; Alternate_Manufacturer: VISHAY SEMICONDUCTOR OPTO DIVISION; Alternate_Internal_Part_Number: MCD-02400; Part_Preference: Recommended; Provided_By: SUBCO; Component_Country_Of_Origin: Unknown; ID: 3155; ShowFields: YES
LNK1 LNK2 LNK4 LNK7 LNK8 LNK11 = MCD-02777: Track link on PCB 200um width for layout routing; Part_Preference: Recommended; Part_Type: Misc; ID: 4889; ShowFields: YES
R2 R46 R57 R59 R60 R81 = MCD-00052: Resistor,0R,0402,5%,1/16W; Manufacturer_Part_Number: RC0402JR-070RL; Manufacturer: YAGEO; Part_Preference: Recommended; ECCN_US: EAR99; ECCN_EU: NEC; Provided_By: SUBCO; Initial_Board_Reference: mb1274; Order_Code_RS: 618-5804; Component_Country_Of_Origin: China; ID: 2540; ShowFields: YES
R210 = MCD-00441: Resistor,270R,0402,1%,1/16W; Manufacturer_Part_Number: RC0402FR-07270RL; Manufacturer: YAGEO; Part_Preference: Recommended; Provided_By: SUBCO; ECCN_US: EAR99; ECCN_EU: NEC; Component_Country_Of_Origin: China; ID: 2838; ShowFields: YES
U26 = MCD-03000: STPMIC2; Part_Type: IC; Part_Preference: Recommended; Manufacturer: STMICROELECTRONICS; Component_Country_Of_Origin: Unknown; ShowFields: YES; ID: 5116

## Sheet STM32MP25XXAI Power.SchDoc: STM32MP25XXAI Power
size A3; Date: Not used; ApprovedBy: Not used; CheckedBy: Not used; Author: Not used; CompanyName: STMicroelectronics; DrawnBy: Not used; Engineer: Not used; Organization: Not used; Address1: Not used; Address2: Not used; Address3: Not used; Address4: Not used; DocumentNumber: 5; Revision: Not used; SheetNumber: 5; SheetTotal: 7
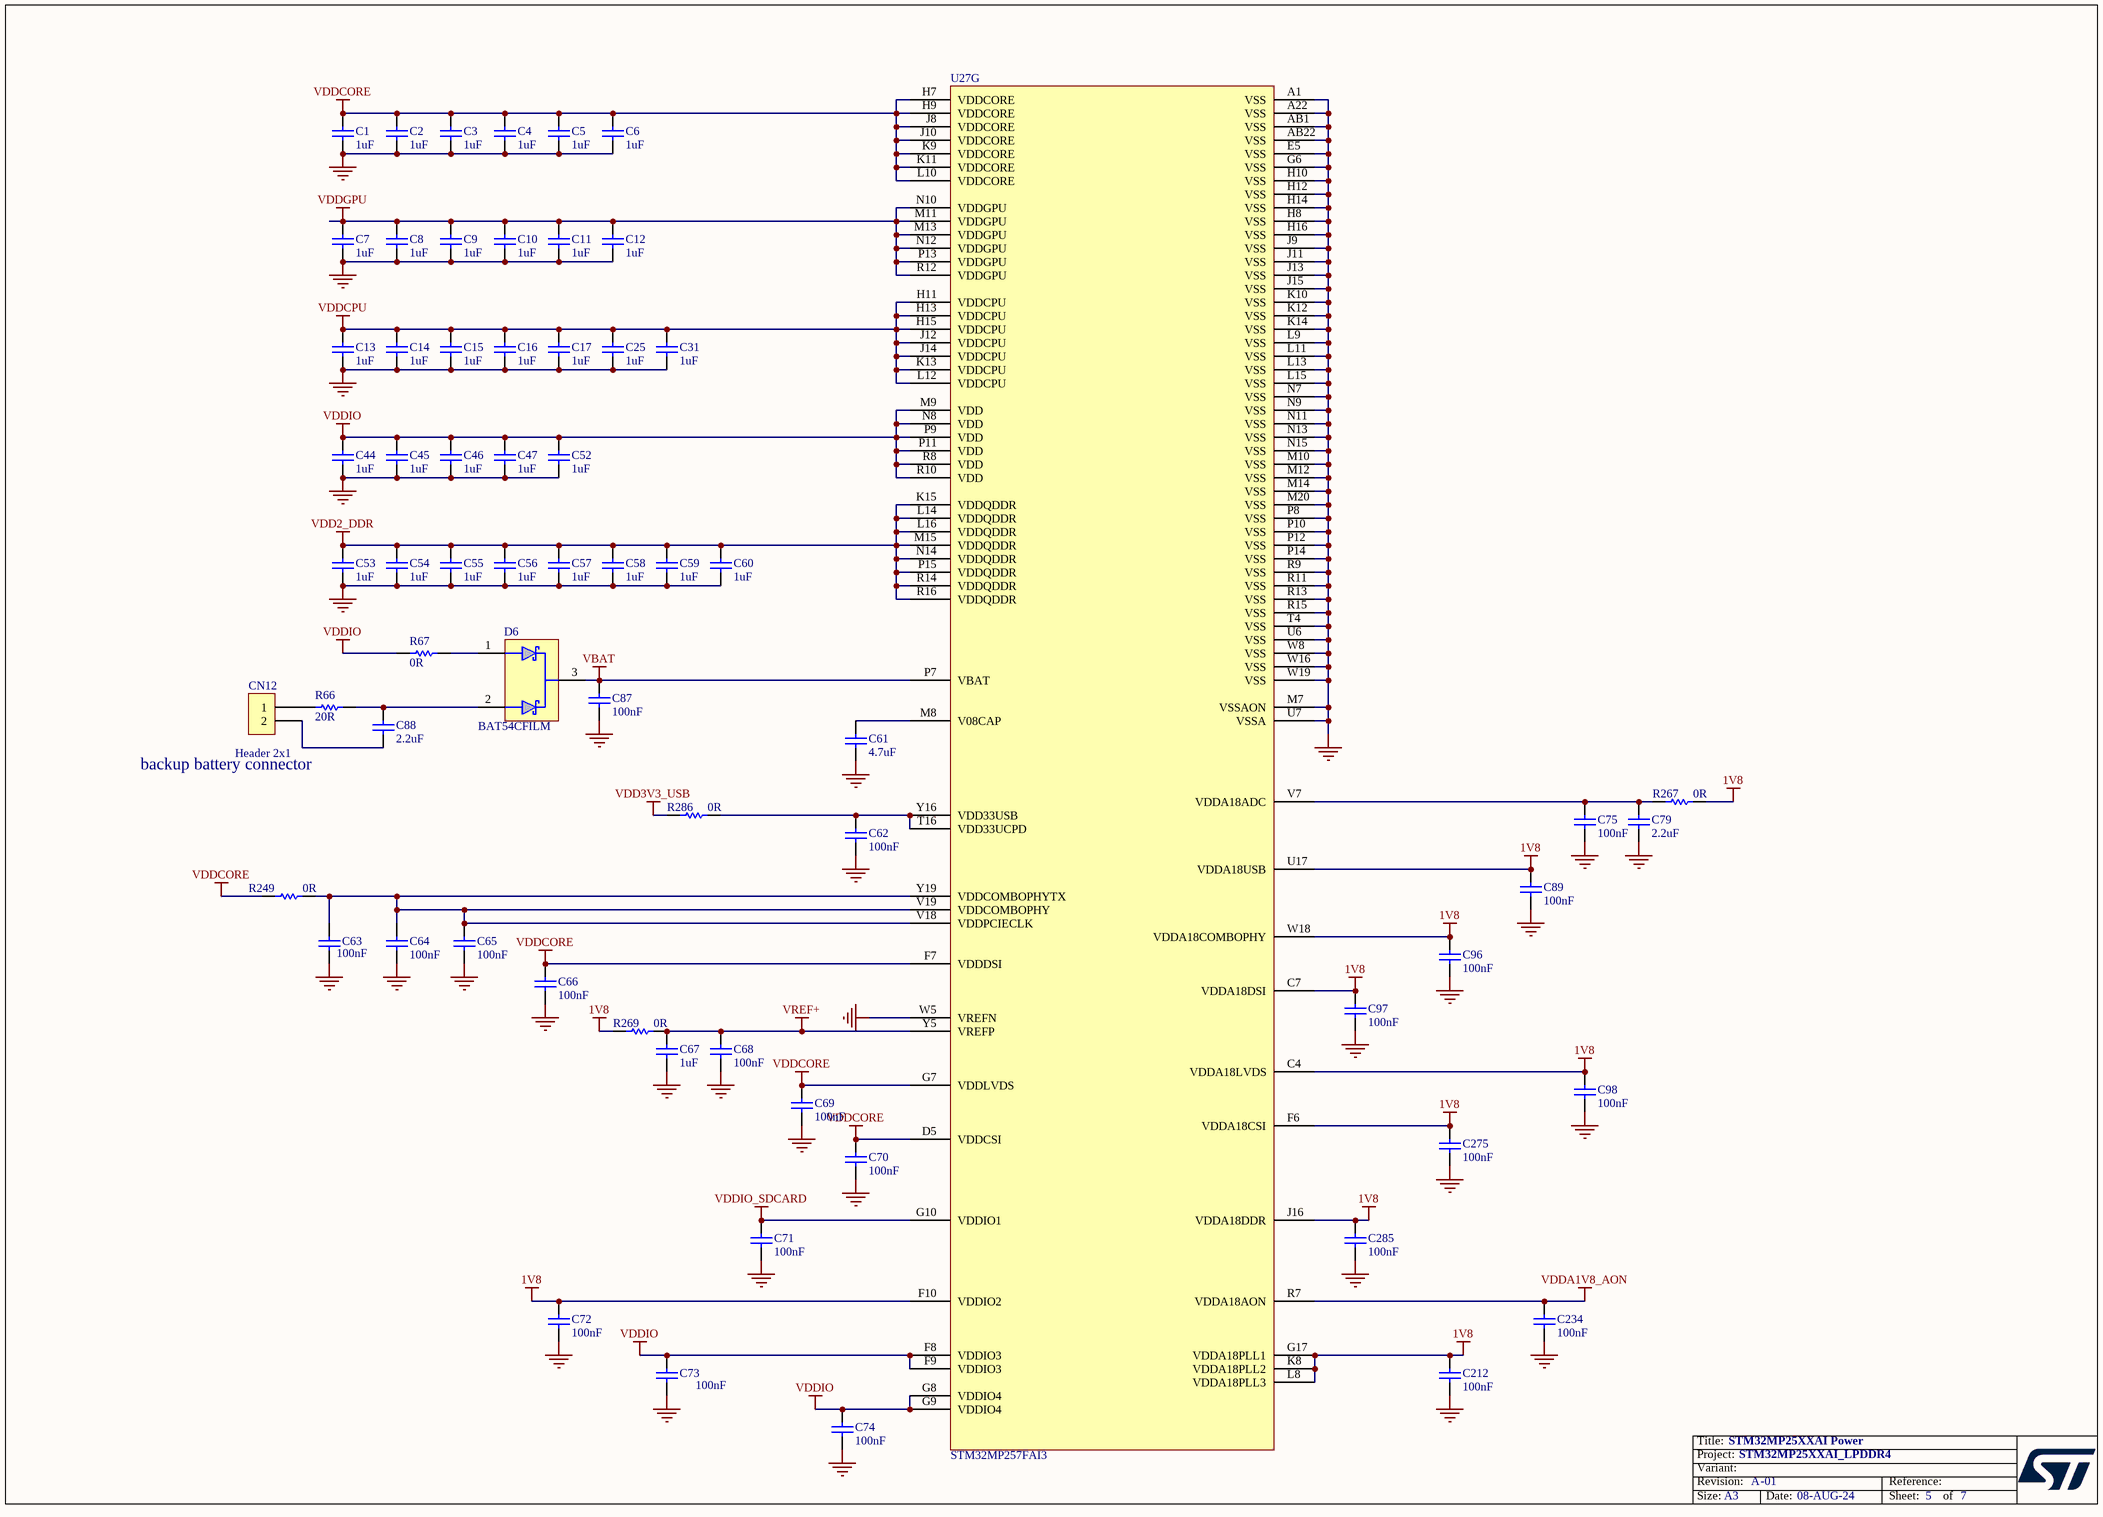
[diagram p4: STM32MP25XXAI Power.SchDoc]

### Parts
C1  value 1uF  [C0201_MURATA_GRM033_H0P3]  (hidden comment: Capacitor)
C2  value 1uF  [C0201_MURATA_GRM033_H0P3]  (hidden comment: Capacitor)
C3  value 1uF  [C0201_MURATA_GRM033_H0P3]  (hidden comment: Capacitor)
C4  value 1uF  [C0201_MURATA_GRM033_H0P3]  (hidden comment: Capacitor)
C5  value 1uF  [C0201_MURATA_GRM033_H0P3]  (hidden comment: Capacitor)
C6  value 1uF  [C0201_MURATA_GRM033_H0P3]  (hidden comment: Capacitor)
C7  value 1uF  [C0201_MURATA_GRM033_H0P3]  (hidden comment: Capacitor)
C8  value 1uF  [C0201_MURATA_GRM033_H0P3]  (hidden comment: Capacitor)
C9  value 1uF  [C0201_MURATA_GRM033_H0P3]  (hidden comment: Capacitor)
C10  value 1uF  [C0201_MURATA_GRM033_H0P3]  (hidden comment: Capacitor)
C11  value 1uF  [C0201_MURATA_GRM033_H0P3]  (hidden comment: Capacitor)
C12  value 1uF  [C0201_MURATA_GRM033_H0P3]  (hidden comment: Capacitor)
C13  value 1uF  [C0201_MURATA_GRM033_H0P3]  (hidden comment: Capacitor)
C14  value 1uF  [C0201_MURATA_GRM033_H0P3]  (hidden comment: Capacitor)
C15  value 1uF  [C0201_MURATA_GRM033_H0P3]  (hidden comment: Capacitor)
C16  value 1uF  [C0201_MURATA_GRM033_H0P3]  (hidden comment: Capacitor)
C17  value 1uF  [C0201_MURATA_GRM033_H0P3]  (hidden comment: Capacitor)
C25  value 1uF  [C0201_MURATA_GRM033_H0P3]  (hidden comment: Capacitor)
C31  value 1uF  [C0201_MURATA_GRM033_H0P3]  (hidden comment: Capacitor)
C44  value 1uF  [C0201_MURATA_GRM033_H0P3]  (hidden comment: Capacitor)
C45  value 1uF  [C0201_MURATA_GRM033_H0P3]  (hidden comment: Capacitor)
C46  value 1uF  [C0201_MURATA_GRM033_H0P3]  (hidden comment: Capacitor)
C47  value 1uF  [C0201_MURATA_GRM033_H0P3]  (hidden comment: Capacitor)
C52  value 1uF  [C0201_MURATA_GRM033_H0P3]  (hidden comment: Capacitor)
C53  value 1uF  [C0201_MURATA_GRM033_H0P3]  (hidden comment: Capacitor)
C54  value 1uF  [C0201_MURATA_GRM033_H0P3]  (hidden comment: Capacitor)
C55  value 1uF  [C0201_MURATA_GRM033_H0P3]  (hidden comment: Capacitor)
C56  value 1uF  [C0201_MURATA_GRM033_H0P3]  (hidden comment: Capacitor)
C57  value 1uF  [C0201_MURATA_GRM033_H0P3]  (hidden comment: Capacitor)
C58  value 1uF  [C0201_MURATA_GRM033_H0P3]  (hidden comment: Capacitor)
C59  value 1uF  [C0201_MURATA_GRM033_H0P3]  (hidden comment: Capacitor)
C60  value 1uF  [C0201_MURATA_GRM033_H0P3]  (hidden comment: Capacitor)
C61  value 4.7uF  [C0201_H0P5]  (hidden comment: Capacitor)
C62  value 100nF  [C0201_MURATA_GRM033_H0P3]  (hidden comment: Capacitor)
C63  value 100nF  [C0201_MURATA_GRM033_H0P3]  (hidden comment: Capacitor)
C64  value 100nF  [C0201_MURATA_GRM033_H0P3]  (hidden comment: Capacitor)
C65  value 100nF  [C0201_MURATA_GRM033_H0P3]  (hidden comment: Capacitor)
C66  value 100nF  [C0201_MURATA_GRM033_H0P3]  (hidden comment: Capacitor)
C67  value 1uF  [C0201_MURATA_GRM033_H0P3]  (hidden comment: Capacitor)
C68  value 100nF  [C0201_MURATA_GRM033_H0P3]  (hidden comment: Capacitor)
C69  value 100nF  [C0201_MURATA_GRM033_H0P3]  (hidden comment: Capacitor)
C70  value 100nF  [C0201_MURATA_GRM033_H0P3]  (hidden comment: Capacitor)
C71  value 100nF  [C0201_MURATA_GRM033_H0P3]  (hidden comment: Capacitor)
C72  value 100nF  [C0201_MURATA_GRM033_H0P3]  (hidden comment: Capacitor)
C73  value 100nF  [C0201_MURATA_GRM033_H0P3]  (hidden comment: Capacitor)
C74  value 100nF  [C0201_MURATA_GRM033_H0P3]  (hidden comment: Capacitor)
C75  value 100nF  [C0201_MURATA_GRM033_H0P3]  (hidden comment: Capacitor)
C79  value 2.2uF  [C0201_H0P5]  (hidden comment: Capacitor)
C87  value 100nF  [C0402]
C88  value 2.2uF  [C0402]  (hidden comment: Capacitor)
C89  value 100nF  [C0201_MURATA_GRM033_H0P3]  (hidden comment: Capacitor)
C96  value 100nF  [C0201_MURATA_GRM033_H0P3]  (hidden comment: Capacitor)
C97  value 100nF  [C0201_MURATA_GRM033_H0P3]  (hidden comment: Capacitor)
C98  value 100nF  [C0201_MURATA_GRM033_H0P3]  (hidden comment: Capacitor)
C212  value 100nF  [C0201_MURATA_GRM033_H0P3]  (hidden comment: Capacitor)
C234  value 100nF  [C0201_MURATA_GRM033_H0P3]  (hidden comment: Capacitor)
C275  value 100nF  [C0201_MURATA_GRM033_H0P3]  (hidden comment: Capacitor)
C285  value 100nF  [C0201_MURATA_GRM033_H0P3]  (hidden comment: Capacitor)
CN12  value Header 2x1  [CON_MOLEX_53047-0210]
D6  value BAT54CFILM  [DIO_SOT23]  (hidden comment: DIODE_3P_DUAL_COMMON_CATHODE)
R66  value 20R  [R0402]  (hidden comment: Resistor)
R67  value 0R  [R0402]  (hidden comment: Resistor)
R249  value 0R  [R0603]  (hidden comment: Resistor)
R267  value 0R  [R0402]
R269  value 0R  [R0402]
R286  value 0R  [R0402]
U27  STM32MP257FAI3  [ICC_LFBGA436_18X18_P080_H1P70_STM32MP257_CODE-B0D1]  (part G of 9)

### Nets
1V8: C72.2 C89.2 C96.2 C97.2 C98.2 C212.2 C275.2 C285.2 R267.2 R269.1 U27.C4(VDDA18LVDS) U27.C7(VDDA18DSI) U27.F6(VDDA18CSI) U27.F10(VDDIO2) U27.G17(VDDA18PLL1) U27.J16(VDDA18DDR) U27.K8(VDDA18PLL2) U27.L8(VDDA18PLL3) U27.U17(VDDA18USB) U27.W18(VDDA18COMBOPHY)
GND: C1.2 C2.1 C3.1 C4.2 C5.1 C6.1 C7.1 C8.1 C9.1 C10.1 C11.2 C12.1 C13.2 C14.1 C15.1 C16.2 C17.1 C25.1 C31.1 C44.2 C45.1 C46.1 C47.2 C52.1 C53.1 C54.2 C55.1 C56.1 C57.1 C58.1 C59.1 C60.1 C61.1 C62.1 C63.1 C64.1 C65.1 C66.1 C67.1 C68.1 C69.1 C70.1 C71.1 C72.1 C73.1 C74.1 C75.1 C79.1 C87.1 C89.1 C96.1 C97.1 C98.1 C212.1 C234.1 C275.1 C285.1 U27.A1(VSS) U27.A22(VSS) U27.AB1(VSS) U27.AB22(VSS) U27.E5(VSS) U27.G6(VSS) U27.H8(VSS) U27.H10(VSS) U27.H12(VSS) U27.H14(VSS) U27.H16(VSS) U27.J9(VSS) U27.J11(VSS) U27.J13(VSS) U27.J15(VSS) U27.K10(VSS) U27.K12(VSS) U27.K14(VSS) U27.L9(VSS) U27.L11(VSS) U27.L13(VSS) U27.L15(VSS) U27.M7(VSSAON) U27.M10(VSS) U27.M12(VSS) U27.M14(VSS) U27.M20(VSS) U27.N7(VSS) U27.N9(VSS) U27.N11(VSS) U27.N13(VSS) U27.N15(VSS) U27.P8(VSS) U27.P10(VSS) U27.P12(VSS) U27.P14(VSS) U27.R9(VSS) U27.R11(VSS) U27.R13(VSS) U27.R15(VSS) U27.T4(VSS) U27.U6(VSS) U27.U7(VSSA) U27.W5(VREFN) U27.W8(VSS) U27.W16(VSS) U27.W19(VSS)
VBAT: C87.2 D6.3 U27.P7(VBAT)
VDD2_DDR: C53.2 C54.1 C55.2 C56.2 C57.2 C58.2 C59.2 C60.2 U27.K15(VDDQDDR) U27.L14(VDDQDDR) U27.L16(VDDQDDR) U27.M15(VDDQDDR) U27.N14(VDDQDDR) U27.P15(VDDQDDR) U27.R14(VDDQDDR) U27.R16(VDDQDDR)
VDD3V3_USB: R286.1
VDDA1V8_AON: C234.2 U27.R7(VDDA18AON)
VDDCORE: C1.1 C2.2 C3.2 C4.1 C5.2 C6.2 C66.2 C69.2 C70.2 R249.1 U27.D5(VDDCSI) U27.F7(VDDDSI) U27.G7(VDDLVDS) U27.H7(VDDCORE) U27.H9(VDDCORE) U27.J8(VDDCORE) U27.J10(VDDCORE) U27.K9(VDDCORE) U27.K11(VDDCORE) U27.L10(VDDCORE)
VDDCPU: C13.1 C14.2 C15.2 C16.1 C17.2 C25.2 C31.2 U27.H11(VDDCPU) U27.H13(VDDCPU) U27.H15(VDDCPU) U27.J12(VDDCPU) U27.J14(VDDCPU) U27.K13(VDDCPU) U27.L12(VDDCPU)
VDDGPU: C7.2 C8.2 C9.2 C10.2 C11.1 C12.2 U27.M11(VDDGPU) U27.M13(VDDGPU) U27.N10(VDDGPU) U27.N12(VDDGPU) U27.P13(VDDGPU) U27.R12(VDDGPU)
VDDIO: C44.1 C45.2 C46.2 C47.1 C52.2 C73.2 C74.2 R67.2 U27.F8(VDDIO3) U27.F9(VDDIO3) U27.G8(VDDIO4) U27.G9(VDDIO4) U27.M9(VDD) U27.N8(VDD) U27.P9(VDD) U27.P11(VDD) U27.R8(VDD) U27.R10(VDD)
VDDIO_SDCARD: C71.2 U27.G10(VDDIO1)
VREF+: C67.2 C68.2 R269.2 U27.Y5(VREFP)
NetC61_2: C61.2 U27.M8(V08CAP)
NetC62_2: C62.2 R286.2 U27.T16(VDD33UCPD) U27.Y16(VDD33USB)
NetC63_2: C63.2 C64.2 C65.2 R249.2 U27.V18(VDDPCIECLK) U27.V19(VDDCOMBOPHY) U27.Y19(VDDCOMBOPHYTX)
NetC75_2: C75.2 C79.2 R267.1 U27.V7(VDDA18ADC)
NetC88_1: C88.1 CN12.2
NetC88_2: C88.2 D6.2 R66.2
NetCN12_1: CN12.1 R66.1
NetD6_1: D6.1 R67.1

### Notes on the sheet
- backup battery connector

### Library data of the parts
C1-C17 C25 C31 C44-C47 C52-C60 C67 = MCD-02377: Capacitor, MLCC, 1uF, 6.3V, X5R, +/-20%, 0201, T=0,3mm; Manufacturer_Part_Number: GRM033R60J105MEA2; Manufacturer: MURATA; Part_Preference: Recommended; Order_Code_RS: 820-0643
C61 = MCD-01534: Capacitor, MLCC, 4,7uF, 6V3, X5R, +/-20%, 0201, T=0.5mm; Part_Preference: Recommended; Manufacturer: MURATA; Manufacturer_Part_Number: GRM035R60J475ME15
C62-C66 C68-C75 C89 C96-C98 C212 C234 C275 C285 = MCD-01535: Capacitor, MLCC,100nF, 10V, X7R, +/-10%, 0201, T=0.3mm; Part_Preference: Recommended; Manufacturer: MURATA; Manufacturer_Part_Number: GRM033R61A104KE15; Order_Code_RS: 790-2742
C79 = MCD-02235: Capacitor, MLCC, 2.2uF, 10V, X5R,+/-10%, 0201, T=0.5mm; Part_Preference: Recommended; Manufacturer: MURATA; Manufacturer_Part_Number: GRM033R61A225KE47D; Order_Code_RS: NA; Component_Country_Of_Origin: Japan; ShowFields: YES; ID: 4335
C87 = MCD-00006: Capacitor,100nF,16V,X7R,10%,0402; Manufacturer_Part_Number: CC0402KRX7R7BB104; Manufacturer: YAGEO; Alternate_Manufacturer: MURATA; Alternate_Manufacturer_Part_Number: GCM155R71C104KA55D; Part_Preference: Recommended; Partial_Alternate_Internal_Part_Number: MCD-03299; Provided_By: SUBCO; Initial_Board_Reference: MB1274; Order_Code_RS: 616-9701; Component_Country_Of_Origin: China; ID: 2474; ShowFields: YES; Alternate_EMS: M
C88 = MCD-01823: Capacitor, MLCC, 2.2uF, 6V3, X5R,+/-10%, 0402, T=0.5mm; Part_Preference: Recommended; Manufacturer: MURATA; Manufacturer_Part_Number: GRM155R60J225KE95D; Order_Code_RS: 172-6478; Component_Country_Of_Origin: Japan; ID: 3923; ShowFields: YES
CN12 = MCD-00655: Header 2 circuits, 1.25mm Pitch ,  Vertical, with Friction Lock; Part_Type: Connector; Manufacturer_Part_Number: 53047-0210; Manufacturer: MOLEX; BMS_Part_Number: 9083002; Part_Preference: Recommended; Provided_By: SUBCO; Initial_Board_Reference: MB1272; Order_Code_RS: 279-9213; Component_Country_Of_Origin: Unknown; ID: 3091; ShowFields: YES
D6 = MCD-03280: Diode, Schottky, Dual Common Cathode, 0V3, 300mA, 40V, SOT-23; Part_Preference: Recommended; Manufacturer: STMICROELECTRONICS; Full_Alternate_Internal_Part_Number: BAT54C+, BAT54CLT1G, BAT54C-7-F, BAT54C,215; Order_code_RS: 795-8397; Component_Country_Of_Origin: China; ShowFields: YES; ID: 5396
R66 = MCD-00058: Resistor, 20R, 0402, +/-1%, 1/16W; BMS_Part_Number: 9131027; Part_Preference: Recommended; Manufacturer: YAGEO; Manufacturer_Part_Number: RC0402FR-0720RL; Component_Country_Of_Origin: China; ID: 2537; ShowFields: YES
R67 = MCD-00052: Resistor, 0R, 0402, +/-5%, 1/16W; Manufacturer_Part_Number: RC0402JR-070RL; Manufacturer: YAGEO; Part_Preference: Recommended; Order_Code_RS: 618-5804; Component_Country_Of_Origin: China; ShowFields: YES; ID: 2540
R249 = MCD-00056: Resistor, 0R, 0603, +/-5%, 1/10W; Part_Preference: Recommended; Manufacturer: YAGEO; Manufacturer_Part_Number: RC0603JR-070RL; Component_Country_Of_Origin: China; ShowFields: YES; ID: 2536
R267 R269 R286 = MCD-00052: Resistor,0R,0402,5%,1/16W; Manufacturer_Part_Number: RC0402JR-070RL; Manufacturer: YAGEO; Part_Preference: Recommended; ECCN_US: EAR99; ECCN_EU: NEC; Provided_By: SUBCO; Initial_Board_Reference: mb1274; Order_Code_RS: 618-5804
U27 = MCD-02000: as U27 on sheet STM32MP25XXAI I_Os

## Sheet eMMC.SchDoc: eMMC
size A3; Date: Not used; ApprovedBy: Not used; CheckedBy: Not used; Author: Not used; CompanyName: STMicroelectronics; DrawnBy: Not used; Engineer: Not used; Organization: Not used; Address1: Not used; Address2: Not used; Address3: Not used; Address4: Not used; DocumentNumber: 7; Revision: Not used; SheetNumber: 7; SheetTotal: 7
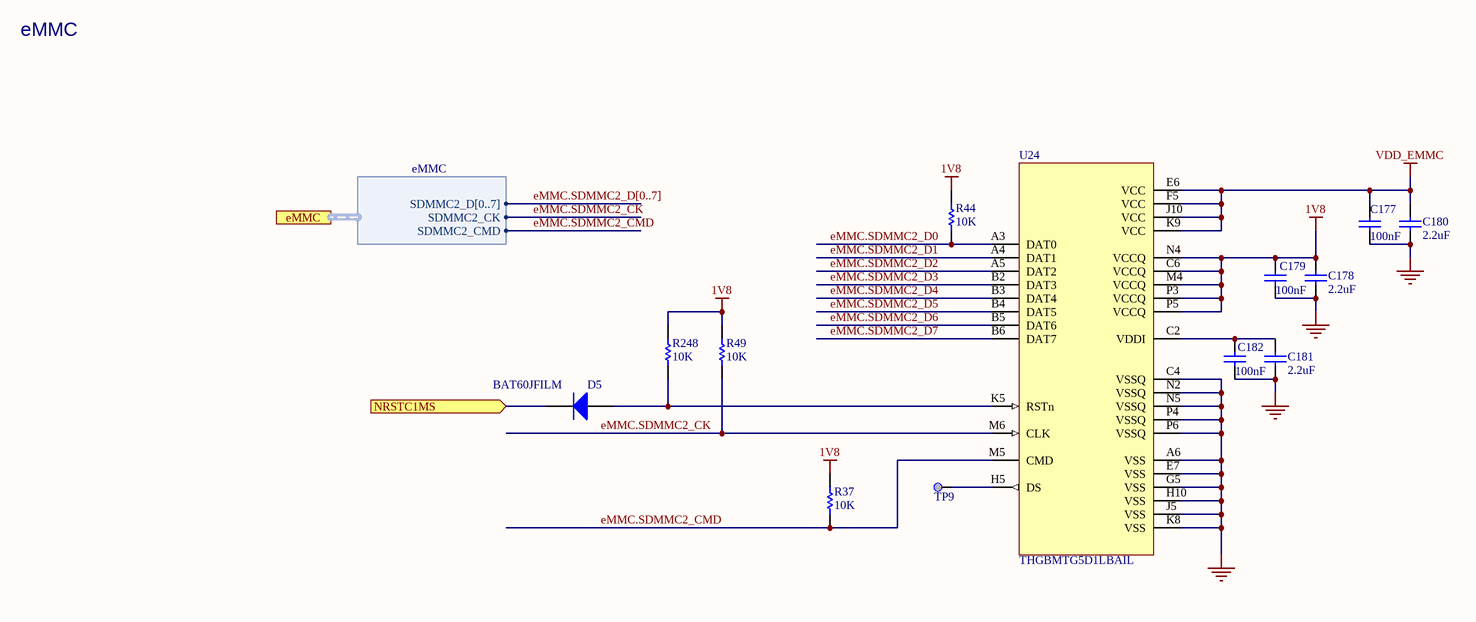
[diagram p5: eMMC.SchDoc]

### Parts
C177  value 100nF  [C0402]  (hidden comment: Capacitor)
C178  value 2.2uF  [C0402]  (hidden comment: Capacitor)
C179  value 100nF  [C0402]  (hidden comment: Capacitor)
C180  value 2.2uF  [C0402]  (hidden comment: Capacitor)
C181  value 2.2uF  [C0402]  (hidden comment: Capacitor)
C182  value 100nF  [C0402]  (hidden comment: Capacitor)
D5  BAT60JFILM  [DIO_SOD323]
R37  value 10K  [R0402]  (hidden comment: Resistor)
R44  value 10K  [R0402]  (hidden comment: Resistor)
R49  value 10K  [R0402]  (hidden comment: Resistor)
R248  value 10K  [R0402]  (hidden comment: Resistor)
TP9  Test Point  [TP_SMD_1MM]  (value not drawn)  (no BOM)
U24  value THGBMTG5D1LBAIL  [ICC_P-WFBGA153_13X11P5_P050]  (hidden comment: eMMC_THGBMTG5D1LBAIL)

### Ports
eMMC (harness eMMC), NRSTC1MS (in)

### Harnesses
eMMC: SDMMC2_CK, SDMMC2_CMD, SDMMC2_D[0..7]

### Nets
1V8: C178.2 C179.2 R37.2 R44.2 R49.2 R248.2 U24.C6(VCCQ) U24.M4(VCCQ) U24.N4(VCCQ) U24.P3(VCCQ) U24.P5(VCCQ)
GND: C177.1 C178.1 C179.1 C180.1 C181.1 C182.1 U24.A6(VSS) U24.C4(VSSQ) U24.E7(VSS) U24.G5(VSS) U24.H10(VSS) U24.J5(VSS) U24.K8(VSS) U24.N2(VSSQ) U24.N5(VSSQ) U24.P4(VSSQ) U24.P6(VSSQ)
VDD_EMMC: C177.2 C180.2 U24.E6(VCC) U24.F5(VCC) U24.J10(VCC) U24.K9(VCC)
eMMC.SDMMC2_CK: R49.1 U24.M6(CLK) ; port eMMC.SDMMC2_CK
eMMC.SDMMC2_CMD: R37.1 U24.M5(CMD) ; port eMMC.SDMMC2_CMD
eMMC.SDMMC2_D0: R44.1 U24.A3(DAT0)
eMMC.SDMMC2_D1: U24.A4(DAT1)
eMMC.SDMMC2_D2: U24.A5(DAT2)
eMMC.SDMMC2_D3: U24.B2(DAT3)
eMMC.SDMMC2_D4: U24.B3(DAT4)
eMMC.SDMMC2_D5: U24.B4(DAT5)
eMMC.SDMMC2_D6: U24.B5(DAT6)
eMMC.SDMMC2_D7: U24.B6(DAT7)
NRSTC1MS: D5.2(K) ; port NRSTC1MS
NetC181_2: C181.2 C182.2 U24.C2(VDDI)
NetD5_1: D5.1(A) R248.1 U24.K5(RSTn)
NetTP9_1: TP9.1 U24.H5(DS)

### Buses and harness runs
bus eMMC.SDMMC2_D[0..7]

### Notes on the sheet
- eMMC

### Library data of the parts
C177 C179 C182 = MCD-00006: Capacitor, MLCC, 100nF, 16V, X7R, +/-10%, 0402, T=0.5mm; Part_Preference: Recommended; Manufacturer: YAGEO; Manufacturer_Part_Number: CC0402KRX7R7BB104; Alternate_Manufacturer: MURATA; Alternate_Manufacturer_Part_Number: GCM155R71C104KA55D; Order_Code_RS: 616-9701; Component_Country_Of_Origin: China; ID: 2474; ShowFields: YES
C178 C180 C181 = MCD-02606: Capacitor, MLCC, 2.2uF, 6.3V, X5R, +/-10%, 0402, T=0.5mm; Part_Preference: Recommended; Manufacturer: YAGEO; Manufacturer_Part_Number: CC0402KRX5R5BB225; Order_Code_RS: 1992205; ShowFields: YES; ID: 4712
D5 = MCD-00034: BMS_Part_Number: 9151097; Part_Type: Diode; Part_Preference: Recommended; Manufacturer: STMICROELECTRONICS; Manufacturer_HQ_COO: EU; Component_Country_Of_Origin: China; ShowFields: YES; ID: 2483
R37 R44 R49 R248 = MCD-00053: Resistor,10K,0402,1%,1/16W; Manufacturer_Part_Number: RC0402FR-0710KL; Manufacturer: YAGEO; BMS_Part_Number: 9131590; Part_Preference: Recommended; ECCN_US: EAR99; ECCN_EU: NEC; Provided_By: SUBCO; Component_Country_Of_Origin: China; ID: 2539; ShowFields: YES
TP9 = MCD-00074: Test Point 1mm; Part_Type: Misc; Part_Preference: Recommended; ID: 2518; ShowFields: YES
U24 = MCD-02799: Memory, eMMC, 4GB, 15nm ,WFBGA , 153 pins; Part_Type: IC; Part_Preference: Recommended; Manufacturer: KIOXIA; ShowFields: YES; ID: 4911

## Sheet LPDDR4_32bits.SchDoc: LPDDR4
size A3; Date: Not used; ApprovedBy: Not used; CheckedBy: Not used; Author: Not used; CompanyName: STMicroelectronics; DrawnBy: Not used; Engineer: Not used; Organization: Not used; Address1: Not used; Address2: Not used; Address3: Not used; Address4: Not used; DocumentNumber: 6; Revision: Not used; SheetNumber: 6; SheetTotal: 7
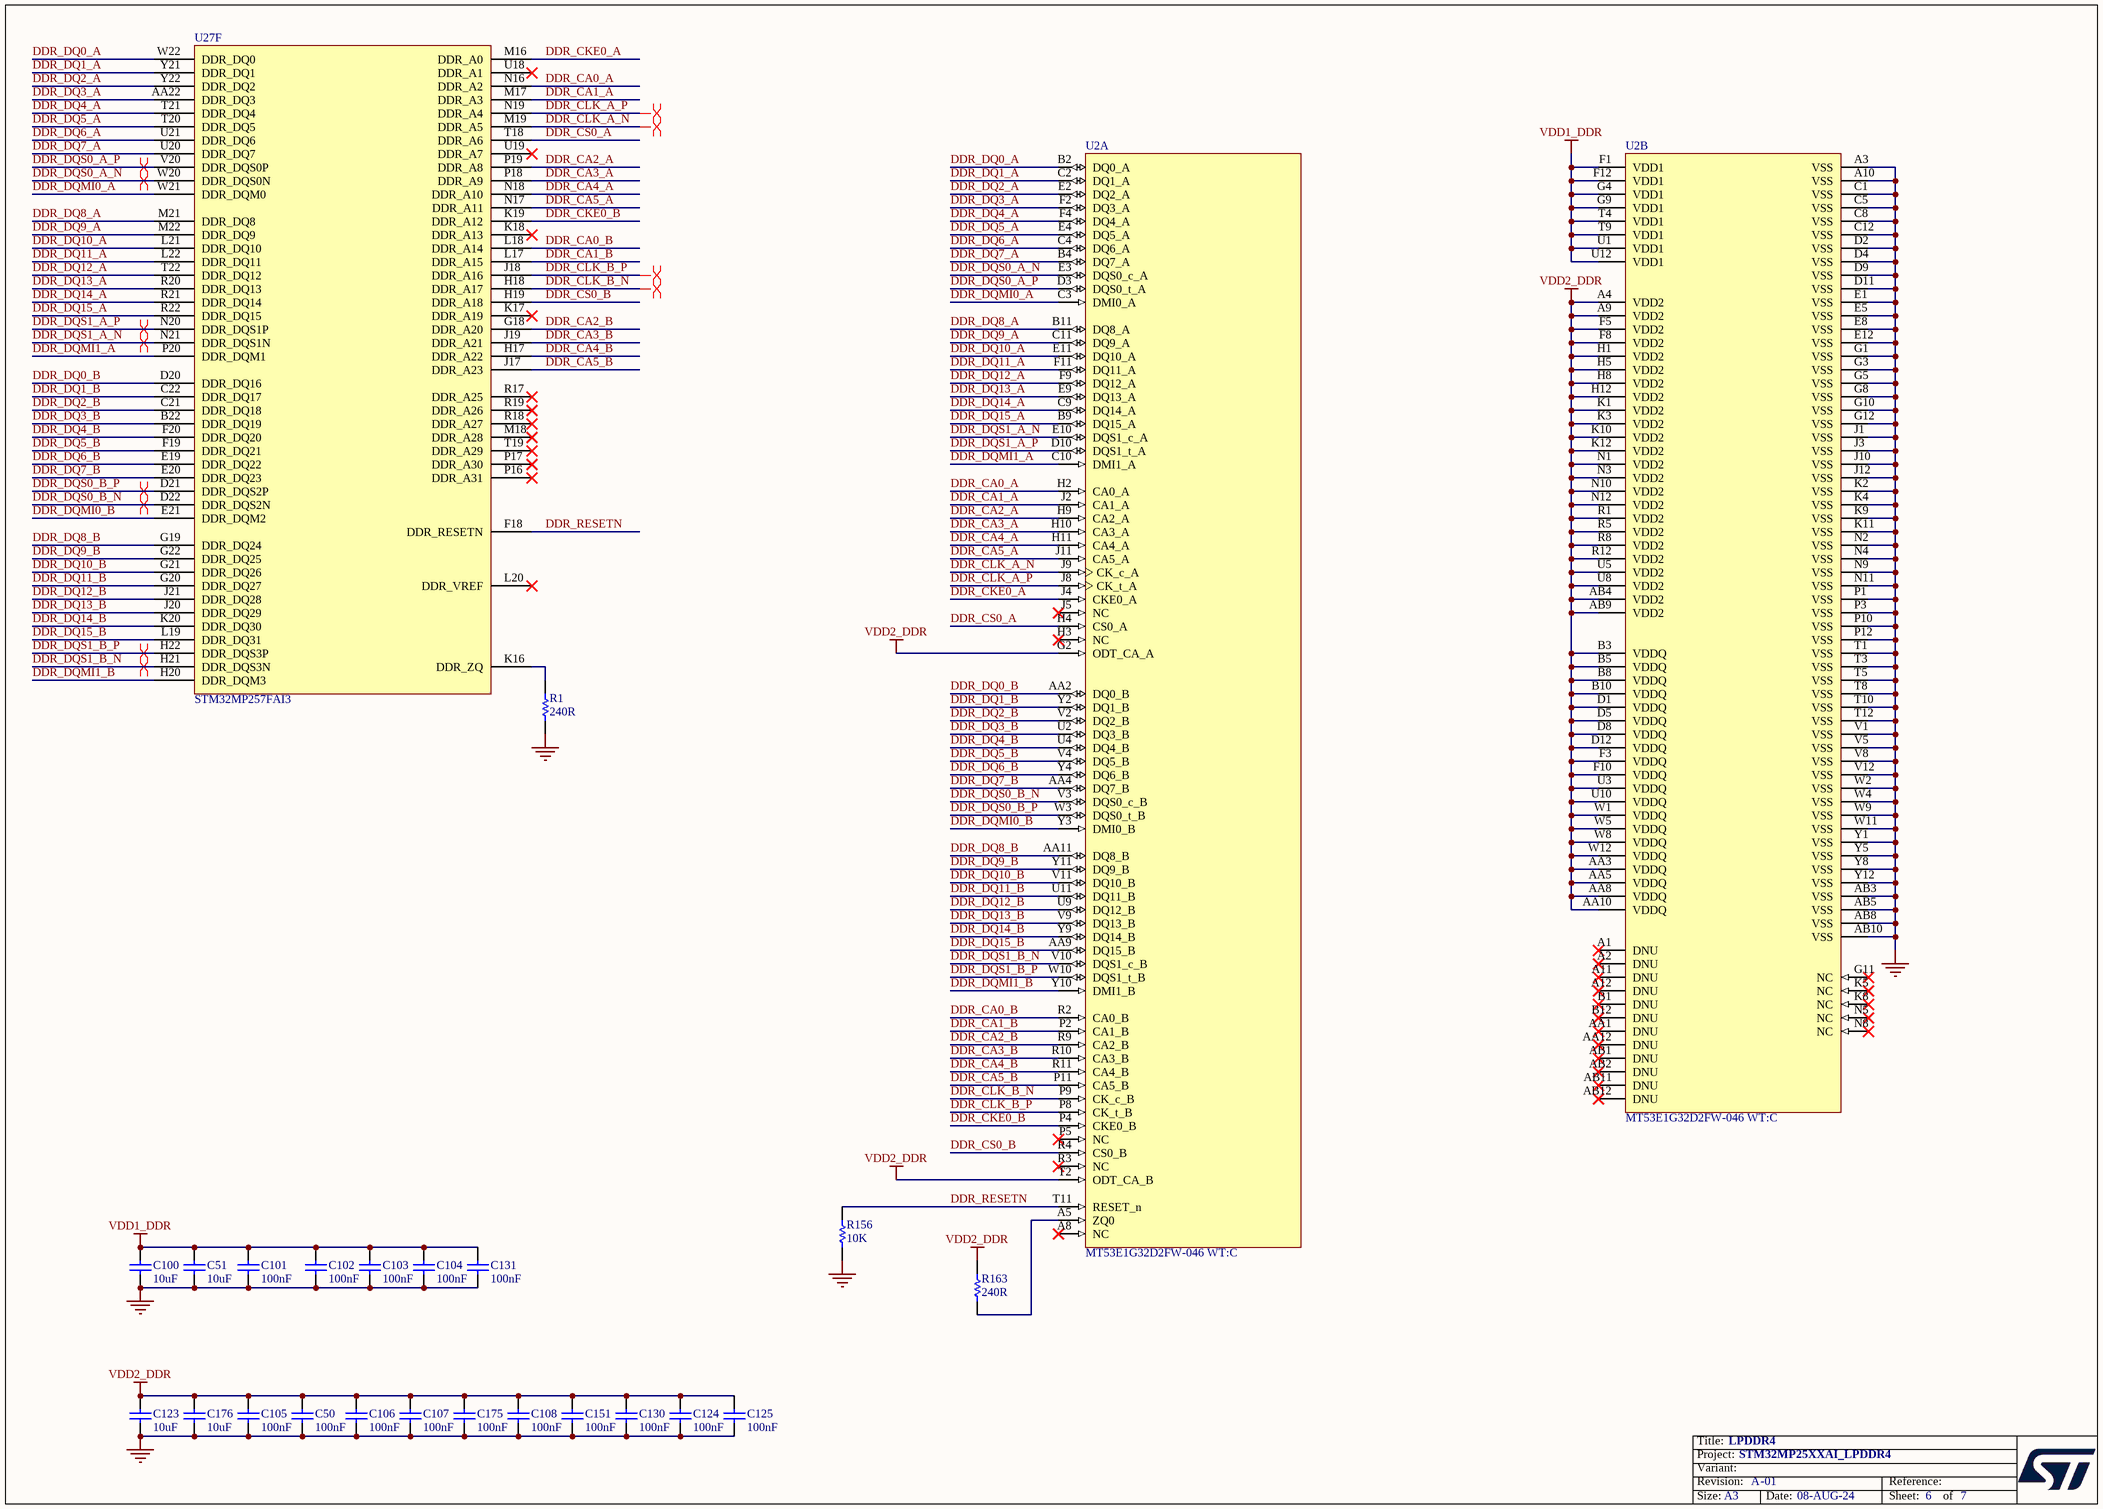
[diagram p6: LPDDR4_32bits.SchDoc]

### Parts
C50  value 100nF  [C0402]  (hidden comment: Capacitor)
C51  value 10uF  [C0603]  (hidden comment: Capacitor)
C100  value 10uF  [C0603]  (hidden comment: Capacitor)
C101  value 100nF  [C0402]  (hidden comment: Capacitor)
C102  value 100nF  [C0402]  (hidden comment: Capacitor)
C103  value 100nF  [C0402]  (hidden comment: Capacitor)
C104  value 100nF  [C0402]  (hidden comment: Capacitor)
C105  value 100nF  [C0402]  (hidden comment: Capacitor)
C106  value 100nF  [C0402]  (hidden comment: Capacitor)
C107  value 100nF  [C0402]  (hidden comment: Capacitor)
C108  value 100nF  [C0402]  (hidden comment: Capacitor)
C123  value 10uF  [C0603]  (hidden comment: Capacitor)
C124  value 100nF  [C0402]  (hidden comment: Capacitor)
C125  value 100nF  [C0402]  (hidden comment: Capacitor)
C130  value 100nF  [C0402]  (hidden comment: Capacitor)
C131  value 100nF  [C0402]  (hidden comment: Capacitor)
C151  value 100nF  [C0402]  (hidden comment: Capacitor)
C175  value 100nF  [C0402]  (hidden comment: Capacitor)
C176  value 10uF  [C0603]  (hidden comment: Capacitor)
R1  value 240R  [R0201_H0P23]  (hidden comment: Resistor)
R156  value 10K  [R0402]  (hidden comment: Resistor)
R163  value 240R  [R0201_H0P23]  (hidden comment: Resistor)
U2  MT53E1G32D2FW-046 WT:C  [ICC_TFBGA200_10X14P5_P080_H1P05_PS0P3]  (parts A,B of 2)
U27  STM32MP257FAI3  [ICC_LFBGA436_18X18_P080_H1P70_STM32MP257_CODE-B0D1]  (part F of 9)

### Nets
GND: C50.2 C51.1 C100.1 C101.1 C102.1 C103.1 C104.1 C105.1 C106.2 C107.2 C108.2 C123.1 C124.2 C125.2 C130.2 C131.1 C151.2 C175.2 C176.1 R1.1 R156.1 U2.A3(VSS) U2.A10(VSS) U2.AB3(VSS) U2.AB5(VSS) U2.AB8(VSS) U2.AB10(VSS) U2.C1(VSS) U2.C5(VSS) U2.C8(VSS) U2.C12(VSS) U2.D2(VSS) U2.D4(VSS) U2.D9(VSS) U2.D11(VSS) U2.E1(VSS) U2.E5(VSS) U2.E8(VSS) U2.E12(VSS) U2.G1(VSS) U2.G3(VSS) U2.G5(VSS) U2.G8(VSS) U2.G10(VSS) U2.G12(VSS) U2.J1(VSS) U2.J3(VSS) U2.J10(VSS) U2.J12(VSS) U2.K2(VSS) U2.K4(VSS) U2.K9(VSS) U2.K11(VSS) U2.N2(VSS) U2.N4(VSS) U2.N9(VSS) U2.N11(VSS) U2.P1(VSS) U2.P3(VSS) U2.P10(VSS) U2.P12(VSS) U2.T1(VSS) U2.T3(VSS) U2.T5(VSS) U2.T8(VSS) U2.T10(VSS) U2.T12(VSS) U2.V1(VSS) U2.V5(VSS) U2.V8(VSS) U2.V12(VSS) U2.W2(VSS) U2.W4(VSS) U2.W9(VSS) U2.W11(VSS) U2.Y1(VSS) U2.Y5(VSS) U2.Y8(VSS) U2.Y12(VSS)
VDD1_DDR: C51.2 C100.2 C101.2 C102.2 C103.2 C104.2 C131.2 U2.F1(VDD1) U2.F12(VDD1) U2.G4(VDD1) U2.G9(VDD1) U2.T4(VDD1) U2.T9(VDD1) U2.U1(VDD1) U2.U12(VDD1)
VDD2_DDR: C50.1 C105.2 C106.1 C107.1 C108.1 C123.2 C124.1 C125.1 C130.1 C151.1 C175.1 C176.2 R163.2 U2.A4(VDD2) U2.A9(VDD2) U2.AA3(VDDQ) U2.AA5(VDDQ) U2.AA8(VDDQ) U2.AA10(VDDQ) U2.AB4(VDD2) U2.AB9(VDD2) U2.B3(VDDQ) U2.B5(VDDQ) U2.B8(VDDQ) U2.B10(VDDQ) U2.D1(VDDQ) U2.D5(VDDQ) U2.D8(VDDQ) U2.D12(VDDQ) U2.F3(VDDQ) U2.F5(VDD2) U2.F8(VDD2) U2.F10(VDDQ) U2.G2(ODT_CA_A) U2.H1(VDD2) U2.H5(VDD2) U2.H8(VDD2) U2.H12(VDD2) U2.K1(VDD2) U2.K3(VDD2) U2.K10(VDD2) U2.K12(VDD2) U2.N1(VDD2) U2.N3(VDD2) U2.N10(VDD2) U2.N12(VDD2) U2.R1(VDD2) U2.R5(VDD2) U2.R8(VDD2) U2.R12(VDD2) U2.T2(ODT_CA_B) U2.U3(VDDQ) U2.U5(VDD2) U2.U8(VDD2) U2.U10(VDDQ) U2.W1(VDDQ) U2.W5(VDDQ) U2.W8(VDDQ) U2.W12(VDDQ)
DDR_CA0_A: U2.H2(CA0_A) U27.N16(DDR_A2)
DDR_CA0_B: U2.R2(CA0_B) U27.L18(DDR_A14)
DDR_CA1_A: U2.J2(CA1_A) U27.M17(DDR_A3)
DDR_CA1_B: U2.P2(CA1_B) U27.L17(DDR_A15)
DDR_CA2_A: U2.H9(CA2_A) U27.P19(DDR_A8)
DDR_CA2_B: U2.R9(CA2_B) U27.G18(DDR_A20)
DDR_CA3_A: U2.H10(CA3_A) U27.P18(DDR_A9)
DDR_CA3_B: U2.R10(CA3_B) U27.J19(DDR_A21)
DDR_CA4_A: U2.H11(CA4_A) U27.N18(DDR_A10)
DDR_CA4_B: U2.R11(CA4_B) U27.H17(DDR_A22)
DDR_CA5_A: U2.J11(CA5_A) U27.N17(DDR_A11)
DDR_CA5_B: U2.P11(CA5_B) U27.J17(DDR_A23)
DDR_CKE0_A: U2.J4(CKE0_A) U27.M16(DDR_A0)
DDR_CKE0_B: U2.P4(CKE0_B) U27.K19(DDR_A12)
DDR_CLK_A_N: U2.J9(CK_c_A) U27.M19(DDR_A5)
DDR_CLK_A_P: U2.J8(CK_t_A) U27.N19(DDR_A4)
DDR_CLK_B_N: U2.P9(CK_c_B) U27.H18(DDR_A17)
DDR_CLK_B_P: U2.P8(CK_t_B) U27.J18(DDR_A16)
DDR_CS0_A: U2.H4(CS0_A) U27.T18(DDR_A6)
DDR_CS0_B: U2.R4(CS0_B) U27.H19(DDR_A18)
DDR_DQ0_A: U2.B2(DQ0_A) U27.W22(DDR_DQ0)
DDR_DQ0_B: U2.AA2(DQ0_B) U27.D20(DDR_DQ16)
DDR_DQ1_A: U2.C2(DQ1_A) U27.Y21(DDR_DQ1)
DDR_DQ1_B: U2.Y2(DQ1_B) U27.C22(DDR_DQ17)
DDR_DQ2_A: U2.E2(DQ2_A) U27.Y22(DDR_DQ2)
DDR_DQ2_B: U2.V2(DQ2_B) U27.C21(DDR_DQ18)
DDR_DQ3_A: U2.F2(DQ3_A) U27.AA22(DDR_DQ3)
DDR_DQ3_B: U2.U2(DQ3_B) U27.B22(DDR_DQ19)
DDR_DQ4_A: U2.F4(DQ4_A) U27.T21(DDR_DQ4)
DDR_DQ4_B: U2.U4(DQ4_B) U27.F20(DDR_DQ20)
DDR_DQ5_A: U2.E4(DQ5_A) U27.T20(DDR_DQ5)
DDR_DQ5_B: U2.V4(DQ5_B) U27.F19(DDR_DQ21)
DDR_DQ6_A: U2.C4(DQ6_A) U27.U21(DDR_DQ6)
DDR_DQ6_B: U2.Y4(DQ6_B) U27.E19(DDR_DQ22)
DDR_DQ7_A: U2.B4(DQ7_A) U27.U20(DDR_DQ7)
DDR_DQ7_B: U2.AA4(DQ7_B) U27.E20(DDR_DQ23)
DDR_DQ8_A: U2.B11(DQ8_A) U27.M21(DDR_DQ8)
DDR_DQ8_B: U2.AA11(DQ8_B) U27.G19(DDR_DQ24)
DDR_DQ9_A: U2.C11(DQ9_A) U27.M22(DDR_DQ9)
DDR_DQ9_B: U2.Y11(DQ9_B) U27.G22(DDR_DQ25)
DDR_DQ10_A: U2.E11(DQ10_A) U27.L21(DDR_DQ10)
DDR_DQ10_B: U2.V11(DQ10_B) U27.G21(DDR_DQ26)
DDR_DQ11_A: U2.F11(DQ11_A) U27.L22(DDR_DQ11)
DDR_DQ11_B: U2.U11(DQ11_B) U27.G20(DDR_DQ27)
DDR_DQ12_A: U2.F9(DQ12_A) U27.T22(DDR_DQ12)
DDR_DQ12_B: U2.U9(DQ12_B) U27.J21(DDR_DQ28)
DDR_DQ13_A: U2.E9(DQ13_A) U27.R20(DDR_DQ13)
DDR_DQ13_B: U2.V9(DQ13_B) U27.J20(DDR_DQ29)
DDR_DQ14_A: U2.C9(DQ14_A) U27.R21(DDR_DQ14)
DDR_DQ14_B: U2.Y9(DQ14_B) U27.K20(DDR_DQ30)
DDR_DQ15_A: U2.B9(DQ15_A) U27.R22(DDR_DQ15)
DDR_DQ15_B: U2.AA9(DQ15_B) U27.L19(DDR_DQ31)
DDR_DQMI0_A: U2.C3(DMI0_A) U27.W21(DDR_DQM0)
DDR_DQMI0_B: U2.Y3(DMI0_B) U27.E21(DDR_DQM2)
DDR_DQMI1_A: U2.C10(DMI1_A) U27.P20(DDR_DQM1)
DDR_DQMI1_B: U2.Y10(DMI1_B) U27.H20(DDR_DQM3)
DDR_DQS0_A_N: U2.E3(DQS0_c_A) U27.W20(DDR_DQS0N)
DDR_DQS0_A_P: U2.D3(DQS0_t_A) U27.V20(DDR_DQS0P)
DDR_DQS0_B_N: U2.V3(DQS0_c_B) U27.D22(DDR_DQS2N)
DDR_DQS0_B_P: U2.W3(DQS0_t_B) U27.D21(DDR_DQS2P)
DDR_DQS1_A_N: U2.E10(DQS1_c_A) U27.N21(DDR_DQS1N)
DDR_DQS1_A_P: U2.D10(DQS1_t_A) U27.N20(DDR_DQS1P)
DDR_DQS1_B_N: U2.V10(DQS1_c_B) U27.H21(DDR_DQS3N)
DDR_DQS1_B_P: U2.W10(DQS1_t_B) U27.H22(DDR_DQS3P)
DDR_RESETN: R156.2 U2.T11(RESET_n) U27.F18(DDR_RESETN)
NetR1_2: R1.2 U27.K16(DDR_ZQ)
NetR163_1: R163.1 U2.A5(ZQ0)

Not connected (* = marked no-connect by the designer): U2 A1(DNU)* A2(DNU)* A8(NC)* A11(DNU)* A12(DNU)* AA1(DNU)* AA12(DNU)* AB1(DNU)* AB2(DNU)* AB11(DNU)* AB12(DNU)* B1(DNU)* B12(DNU)* G11(NC)* H3(NC)* J5(NC)* K5(NC)* K8(NC)* N5(NC)* N8(NC)* P5(NC)* R3(NC)*; U27 K17(DDR_A19)* K18(DDR_A13)* L20(DDR_VREF)* M18(DDR_A28)* P16(DDR_A31)* P17(DDR_A30)* R17(DDR_A25)* R18(DDR_A27)* R19(DDR_A26)* T19(DDR_A29)* U18(DDR_A1)* U19(DDR_A7)*

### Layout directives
differential pair: DDR_CLK_A_N, DDR_CLK_A_P, DDR_CLK_B_N, DDR_CLK_B_P, DDR_DQS0_A_N, DDR_DQS0_A_P, DDR_DQS0_B_N, DDR_DQS0_B_P, DDR_DQS1_A_N, DDR_DQS1_A_P, DDR_DQS1_B_N, DDR_DQS1_B_P

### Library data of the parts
C50 C101-C108 C124 C125 C130 C131 C151 C175 = MCD-00006: Capacitor, MLCC, 100nF, 16V, X7R, +/-10%, 0402, T=0.5mm; Part_Preference: Recommended; Manufacturer: YAGEO; Manufacturer_Part_Number: CC0402KRX7R7BB104; Alternate_Manufacturer: MURATA; Alternate_Manufacturer_Part_Number: GCM155R71C104KA55D; Order_Code_RS: 616-9701
C51 C100 C123 C176 = MCD-01341: Capacitor, MLCC, 10uF, 6V3, X5R, +/-20%, 0603, T=0,8mm; Part_Preference: Recommended; Manufacturer: MURATA; Manufacturer_Part_Number: GRM188R60J106ME47D; Alternate_Manufacturer_Part_Number: GRM188R60J106ME84D
R1 R163 = MCD-02253: Resistor, 240R, 0201, +/-1%, 1/20W; Part_Preference: Recommended; Manufacturer: YAGEO; Manufacturer_Part_Number: RC0201FR-07240RL; Component_Country_Of_Origin: China; ID: 4353; ShowFields: YES
R156 = MCD-00053: Resistor, 10K, 0402, +/-1%, 1/16W; BMS_Part_Number: 9131590; Part_Preference: Recommended; Manufacturer: YAGEO; Manufacturer_Part_Number: RC0402FR-0710KL; Component_Country_Of_Origin: China; ID: 2539; ShowFields: YES
U2 = MCD-04160: Memory, LPDDR4 SDRAM,1V8, 32Gbit, 2133MHz; Part_Type: IC; Part_Preference: Recommended; Manufacturer: MICRON; ShowFields: YES; ID: 6276
U27 = MCD-02000: as U27 on sheet STM32MP25XXAI I_Os

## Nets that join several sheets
1V8: PMIC (5 pins), STM32MP25XXAI Power (20 pins), eMMC (11 pins)
GND: STM32MP25XXAI I_Os (7 pins), PMIC (62 pins), STM32MP25XXAI Power (104 pins), eMMC (17 pins), LPDDR4_32bits (79 pins)
VDD1_DDR: PMIC (C40.2 U26.44), LPDDR4_32bits (15 pins)
VDD2_DDR: PMIC (5 pins), STM32MP25XXAI Power (16 pins), LPDDR4_32bits (59 pins)
VDD3V3_USB: PMIC (C156.2 U26.13), STM32MP25XXAI Power (R286.1)
VDD_EMMC: PMIC (C190.1 U26.16), eMMC (6 pins)
VDDA1V8_AON: STM32MP25XXAI I_Os (U27.T7), PMIC (C189.2 U26.14), STM32MP25XXAI Power (C234.2 U27.R7)
VDDCORE: PMIC (6 pins), STM32MP25XXAI Power (20 pins)
VDDCPU: PMIC (5 pins), STM32MP25XXAI Power (14 pins)
VDDGPU: PMIC (6 pins), STM32MP25XXAI Power (12 pins)
VDDIO: STM32MP25XXAI I_Os (R27.2 R260.2 R261.2), PMIC (6 pins), STM32MP25XXAI Power (18 pins)
VDDIO_SDCARD: PMIC (C217.1 U26.2), STM32MP25XXAI Power (C71.2 U27.G10)
eMMC.SDMMC2_CK: STM32MP25XXAI I_Os (U27.A20), eMMC (R49.1 U24.M6)
eMMC.SDMMC2_CMD: STM32MP25XXAI I_Os (U27.F17), eMMC (R37.1 U24.M5)
eMMC.SDMMC2_D0: STM32MP25XXAI I_Os (U27.B19), eMMC (R44.1 U24.A3)
eMMC.SDMMC2_D1: STM32MP25XXAI I_Os (U27.E17), eMMC (U24.A4)
eMMC.SDMMC2_D2: STM32MP25XXAI I_Os (U27.C18), eMMC (U24.A5)
eMMC.SDMMC2_D3: STM32MP25XXAI I_Os (U27.C19), eMMC (U24.B2)
eMMC.SDMMC2_D4: STM32MP25XXAI I_Os (U27.A19), eMMC (U24.B3)
eMMC.SDMMC2_D5: STM32MP25XXAI I_Os (U27.D18), eMMC (U24.B4)
eMMC.SDMMC2_D6: STM32MP25XXAI I_Os (U27.E16), eMMC (U24.B5)
eMMC.SDMMC2_D7: STM32MP25XXAI I_Os (U27.D17), eMMC (U24.B6)
I2C7.SCL: STM32MP25XXAI I_Os (R261.1 U27.F16), PMIC (U26.33)
I2C7.SDA: STM32MP25XXAI I_Os (R260.1 U27.G15), PMIC (U26.34)
MP257_WAKEUP: STM32MP25XXAI I_Os (U27.Y2), PMIC (U26.32)
NRST: STM32MP25XXAI I_Os (C33.2 U27.U3), PMIC (R81.1)
NRSTC1MS: STM32MP25XXAI I_Os (R27.1 R272.1 U27.T3), PMIC (R59.1), eMMC (D5.2)
PMIC_WAKEUPn: STM32MP25XXAI I_Os (U27.P6), PMIC (R46.1)
PWR_CPU_ON: STM32MP25XXAI I_Os (R272.2 U27.T6), PMIC (R60.1)
PWR_ON: STM32MP25XXAI I_Os (U27.T5), PMIC (R2.1)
